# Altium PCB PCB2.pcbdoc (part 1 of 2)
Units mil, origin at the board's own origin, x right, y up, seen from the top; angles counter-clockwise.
Board outline 4625.8 x 3614.6 mil, 4 copper layers (Top Layer, Inner1, Inner2, Bottom Layer); 121 components, 127 nets, 523 pads, 246 vias.
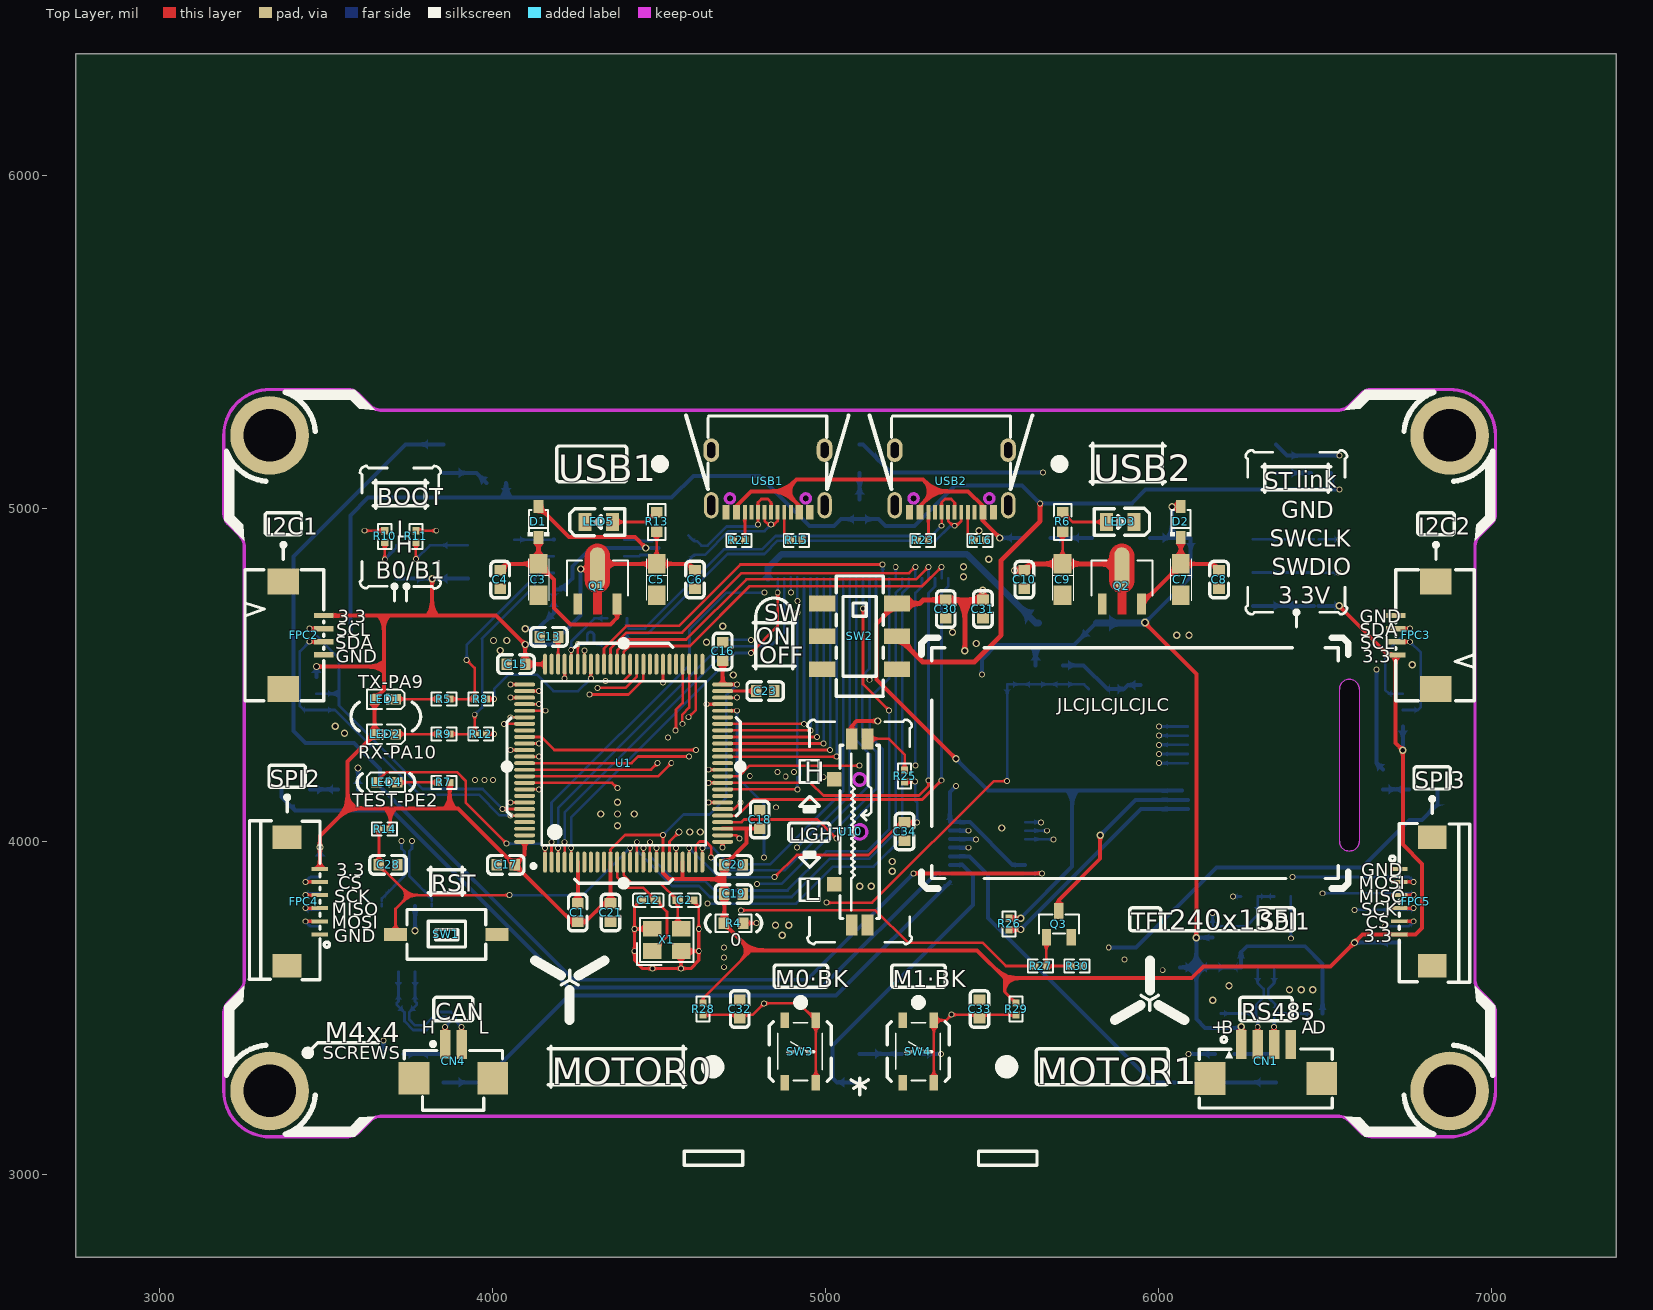
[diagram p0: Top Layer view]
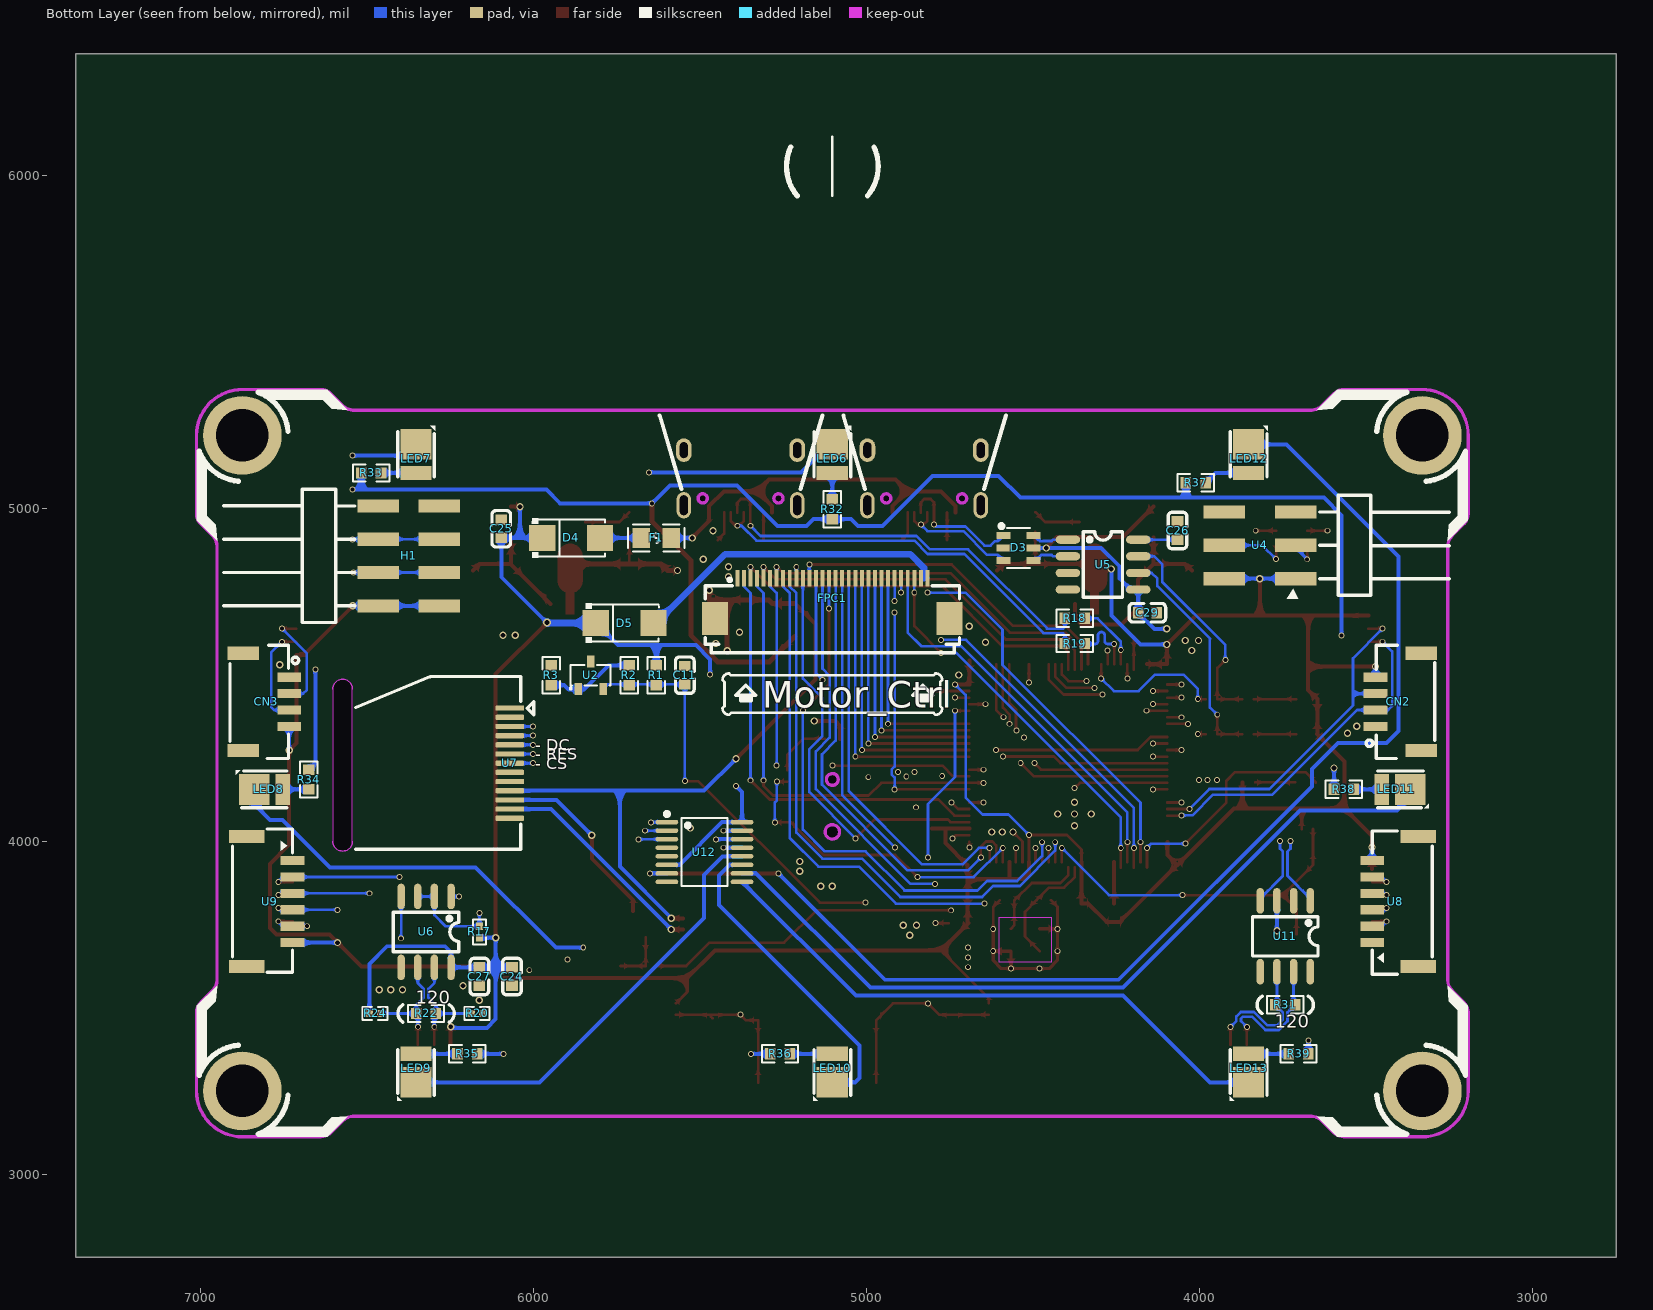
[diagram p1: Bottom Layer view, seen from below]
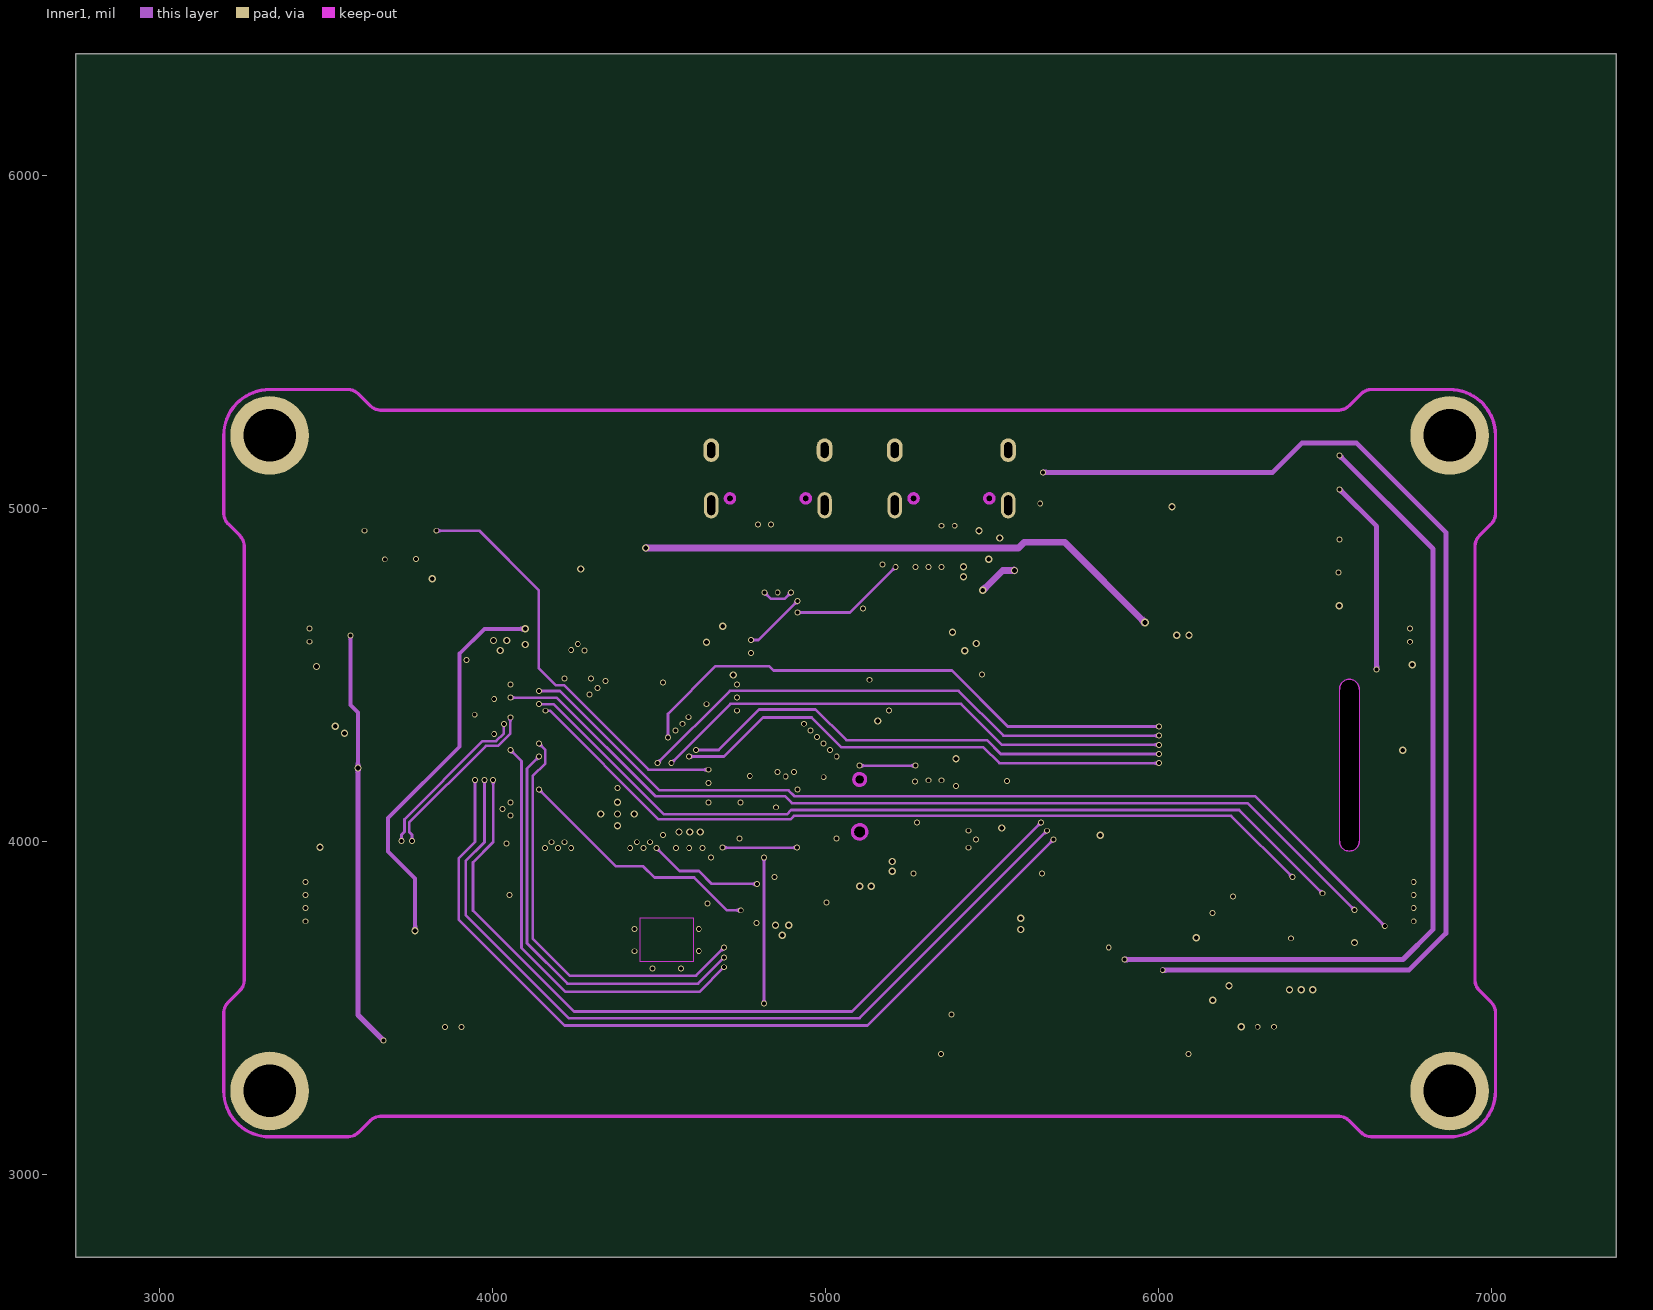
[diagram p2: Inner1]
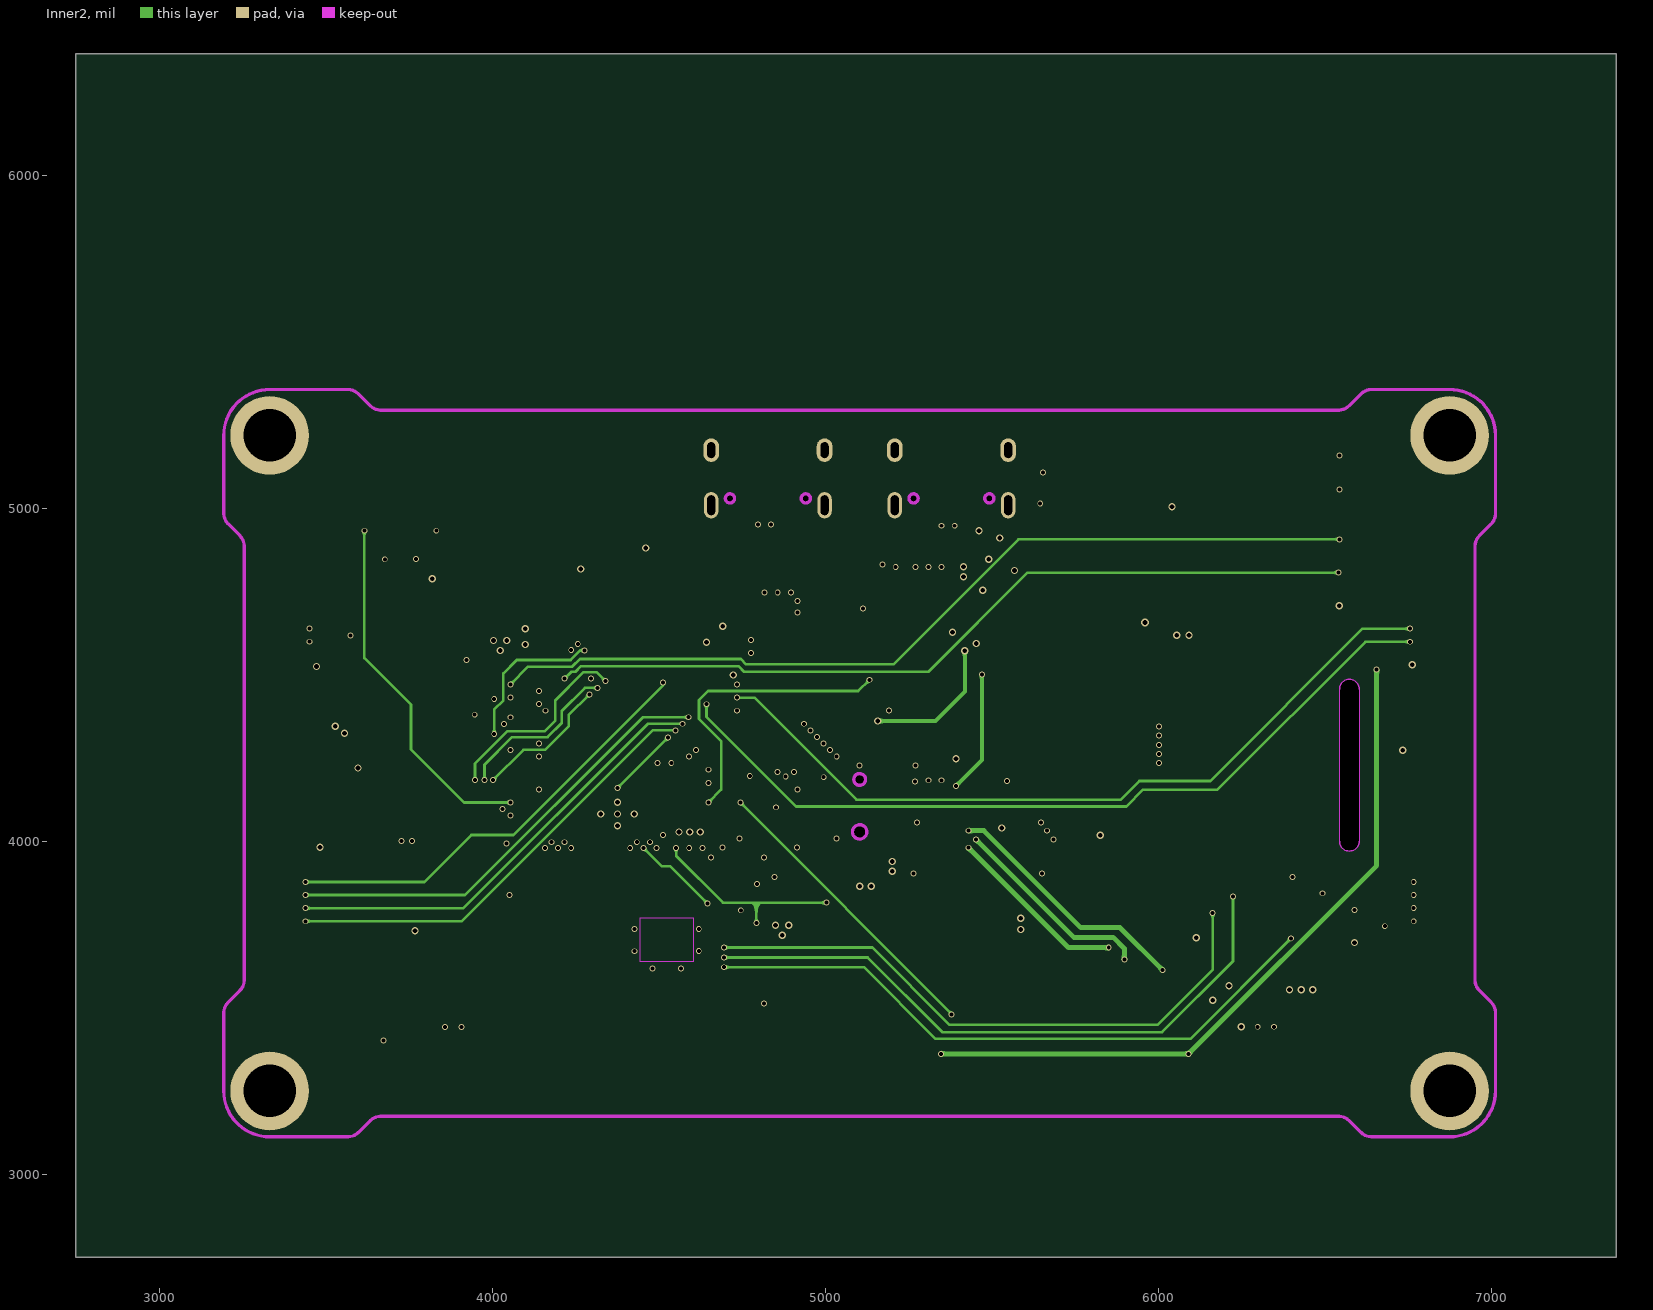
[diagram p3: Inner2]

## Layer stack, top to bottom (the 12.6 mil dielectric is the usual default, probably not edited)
Top Layer: signal copper (thickness not stored)
Dielectric: dielectric 12.6, FR-4, Dk 4.8
Inner1: signal copper (thickness not stored)
Dielectric: dielectric 12.6, FR-4, Dk 4.8
Inner2: signal copper (thickness not stored)
Dielectric: dielectric 12.6, FR-4, Dk 4.8
Bottom Layer: signal copper (thickness not stored)

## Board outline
7375.8,2750 2750,2750 2750,6364.6 7375.8,6364.6

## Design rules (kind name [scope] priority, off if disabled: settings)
BoardOutlineClearance copperThickness1oz [All] p0: genericclearance=10 ignorepadtopadclearanceinfootprint=FALSE except(0: Arc-SplitContinuation Track-SplitContinuation SMDPad-SplitContinuation THPad-SplitContinuation Via-SplitContinuation Fill-SplitContinuation Poly-SplitContinuation Region-SplitContinuation Text-SplitContinuation; 6: Track-CutoutEdge SMDPad-CutoutEdge THPad-CutoutEdge Via-CutoutEdge Region-CutoutEdge; 11.8: Track-OutlineEdge SMDPad-OutlineEdge THPad-OutlineEdge Via-OutlineEdge Fill-OutlineEdge Region-OutlineEdge Poly-OutlineEdge Text-OutlineEdge Fill-CutoutEdge)
BoardOutlineClearance copperThickness2oz [All] p0: genericclearance=10 ignorepadtopadclearanceinfootprint=FALSE except(0: Arc-SplitContinuation Track-SplitContinuation SMDPad-SplitContinuation THPad-SplitContinuation Via-SplitContinuation Fill-SplitContinuation Poly-SplitContinuation Region-SplitContinuation Text-SplitContinuation; 6: Track-CutoutEdge SMDPad-CutoutEdge THPad-CutoutEdge Via-CutoutEdge Region-CutoutEdge; 11.8: Track-OutlineEdge SMDPad-OutlineEdge THPad-OutlineEdge Via-OutlineEdge Fill-OutlineEdge Region-OutlineEdge Poly-OutlineEdge Text-OutlineEdge Fill-CutoutEdge)
Clearance copperThickness1oz [(InNet('+5V') OR InNet('DGND') OR InNet('+3.3V_1') OR InNet('+3.3V_2') OR InNet('$1N11541') OR InNet('$1N5052') OR InNet('OSC_OUT') OR InNet('OSC_IN') OR InNet('$1N13723') OR InNet('VREF') OR InNet('BACKLIGHT_ADC') OR InNet('D+') OR InNet('D-') OR InNet('USB-') OR InNet('USB+') OR InNet('$1N31567') OR InNet('USB_VCC') OR InNet('M1_ADC_C') OR InNet('M1_ADC_A') OR InNet('M1_ADC') OR InNet('M0_ADC') OR InNet('M0_ADC_C') OR InNet('M0_ADC_A') OR InNet('M0_TIM1_CH1N') OR InNet('M0_TIM1_CH1') OR InNet('M0_TIM1_CH2N') OR InNet('M0_TIM1_CH2') OR InNet('M0_TIM1_CH3N') OR InNet('M0_TIM1_CH3') OR InNet('MOTOR_EN1') OR InNet('MOTOR_EN2') OR InNet('$1N25478') OR InNet('$1N25477') OR InNet('CAN_L') OR InNet('CAN_H') OR InNet('$1N8262') OR InNet('$1N34651') OR InNet('$1N34643') OR InNet('$1N34636') OR InNet('$1N4607') OR InNet('$1N21384') OR InNet('$1N21388') OR InNet('BOOT0') OR InNet('BOOT1') OR InNet('OTG_D+') OR InNet('OTG_D-') OR InNet('$1N14257') OR InNet('$1N21387') OR InNet('BACKLIGHT') OR InNet('$1N24716') OR InNet('$1N28487') OR InNet('$1N28620') OR InNet('$1N28747') OR InNet('$1N28749') OR InNet('CH340_TX') OR InNet('CH340_RX') OR InNet('PD6') OR InNet('PD5') OR InNet('PD4') OR InNet('PA14') OR InNet('PA13') OR InNet('PA12') OR InNet('PA11') OR InNet('PC9') OR InNet('PC3') OR InNet('NRST') OR InNet('M1_TIM8_CH1N') OR InNet('M1_TIM8_CH1') OR InNet('M1_TIM8_CH2N') OR InNet('M1_TIM8_CH2') OR InNet('M1_TIM8_CH3N') OR InNet('M1_TIM8_CH3') OR InNet('M0_I2C1_SDA') OR InNet('M0_I2C1_SCL') OR InNet('M1_SPI3_MOSI') OR InNet('M1_SPI3_MISO') OR InNet('M1_SPI3_CS') OR InNet('M1_I2C2_SDA') OR InNet('M1_I2C2_SCL') OR InNet('M1_BK_BUTTON') OR InNet('M0_BK_BUTTON') OR InNet('TEST_LED') OR InNet('$1N41751') OR InNet('PA9') OR InNet('PA10') OR InNet('CAN1_TX') OR InNet('CAN1_RX') OR InNet('$1N56661') OR InNet('M1_SPI3_SCK') OR InNet('M0_BK_OUT') OR InNet('M1_BK_OUT') OR InNet('PB5') OR InNet('PB4') OR InNet('PB3') OR InNet('PD7') OR InNet('PD3') OR InNet('M0_SPI2_CS') OR InNet('M0_SPI2_SCK') OR InNet('M0_SPI2_MISO') OR InNet('M0_SPI2_MOSI') OR InNet('$1N85266') OR InNet('$1N85309') OR InNet('$1N95889') OR InNet('LEDC') OR InNet('LEDB') OR InNet('LEDA') OR InNet('$1N102783') OR InNet('$1N102744') OR InNet('$1N102997') OR InNet('$1N103001') OR InNet('$1N103337') OR InNet('$1N103341') OR InNet('$1N103422') OR InNet('$1N103426') OR InNet('$1N103507') OR InNet('$1N103511') OR InNet('$1N103592') OR InNet('$1N103596') OR InNet('$1N103677') OR InNet('$1N103681') OR InNet('$1N103762') OR InNet('$1N103766') OR InNet('VCC_+3.3V_2') OR InNet('$1N129348') OR InNet('PA7') OR InNet('PA1') OR InNet('PC2'))] p1: gap=7 ignorepadtopadclearanceinfootprint=FALSE except(4: Track-Track; 6: Track-SMDPad SMDPad-SMDPad Track-THPad SMDPad-THPad THPad-THPad Track-Via SMDPad-Via THPad-Via Via-Via SMDPad-Fill THPad-Fill Via-Fill Fill-Fill Track-Region SMDPad-Region THPad-Region Via-Region Region-Region Track-Poly SMDPad-Poly THPad-Poly Via-Poly Fill-Poly Region-Poly Poly-Poly Track-Text SMDPad-Text THPad-Text Via-Text Fill-Text Region-Text Poly-Text Text-Text; 6.9: Track-Hole SMDPad-Hole THPad-Hole Via-Hole Fill-Hole Region-Hole Poly-Hole Text-Hole Sheet-Hole; 11.8: Track-Fill Fill-Region Track-Sheet SMDPad-Sheet THPad-Sheet Via-Sheet Fill-Sheet Region-Sheet Poly-Sheet Text-Sheet)
Clearance copperThickness2oz [All] p1: gap=7 ignorepadtopadclearanceinfootprint=FALSE except(6: Track-SMDPad SMDPad-SMDPad Track-THPad SMDPad-THPad THPad-THPad Track-Via SMDPad-Via THPad-Via Via-Via SMDPad-Fill THPad-Fill Via-Fill Fill-Fill Track-Region SMDPad-Region THPad-Region Via-Region Region-Region Track-Poly SMDPad-Poly THPad-Poly Via-Poly Fill-Poly Region-Poly Poly-Poly Track-Text SMDPad-Text THPad-Text Via-Text Fill-Text Region-Text Poly-Text Text-Text; 6.9: Track-Hole SMDPad-Hole THPad-Hole Via-Hole Fill-Hole Region-Hole Poly-Hole Text-Hole Sheet-Hole; 8: Track-Track; 11.8: Track-Fill Fill-Region Track-Sheet SMDPad-Sheet THPad-Sheet Via-Sheet Fill-Sheet Region-Sheet Poly-Sheet Text-Sheet)
DiffPairsRouting differentialPair [All] p1: maxuncoupledlength=10 minlimit=6 maxlimit=6 mostfreqgap=6 toplayer_minwidth=5 toplayer_prefwidth=10 toplayer_maxwidth=100 bottomlayer_minwidth=5 bottomlayer_prefwidth=10 bottomlayer_maxwidth=100 midlayer1_minwidth=5 midlayer1_prefwidth=10 midlayer1_maxwidth=100 midlayer2_minwidth=5 midlayer2_prefwidth=10 midlayer2_maxwidth=100
PasteMaskExpansion pasteMaskExpansion [All] p1: expansion=0
PlaneConnect innerPlane [All] p1: planeconnectstyle=Relief reliefexpansion=20 reliefentries=4 reliefconductorwidth=10 reliefairgap=10
PolygonConnect copperRegion [All] p1: connectstyle=Direct reliefentries=4 reliefconductorwidth=10 polygonreliefangle="90 Angle" airgapwidth=10
RoutingVias viaSize [All] p1: viastyle="Through Hole" holewidth=12 minholewidth=11.8 maxholewidth=248 width=24 minwidth=17.7 maxwidth=393.7
SolderMaskExpansion solderMaskExpansion [All] p1: useseparateexpansions=TRUE expansion=2 expansionbottom=2
Width copperThickness1oz [All] p1: maxlimit=100 minlimit=5 preferedwidth=10
Width copperThickness2oz [All] p1: maxlimit=100 minlimit=8 preferedwidth=10

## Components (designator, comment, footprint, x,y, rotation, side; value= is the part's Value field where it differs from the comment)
C1 "CL10A105KB8NNNC" C0603 4257.4,3785.7 r90 top
C2 "0402CG140J500NT" C0402 4579.3,3822.79 r0 top
C3 "TAJA226K010RNJ" CASE-A_3216 4139.5,4785.5 r270 top
C4 "CC0603KRX7R9BB104" C0603 4024.5,4785.5 r90 top
C5 "TAJA226K010RNJ" CASE-A_3216 4494.5,4785.5 r270 top
C6 "CC0603KRX7R9BB104" C0603 4609.5,4785.5 r90 top
C7 "TAJA226K010RNJ" CASE-A_3216 6068.31,4785.53 r270 top
C8 "CC0603KRX7R9BB104" C0603 6183.31,4785.53 r90 top
C9 "TAJA226K010RNJ" CASE-A_3216 5713.31,4785.53 r270 top
C10 "CC0603KRX7R9BB104" C0603 5598.31,4785.53 r90 top
C11 "CGA0603X7R104K500JT" C0603 5546.9,4498.6 r270 bottom
C12 "0402CG140J500NT" C0402 4469.3,3822.79 r180 top
C13 "CL10A225KO8NNNC" C0603 4170.74,4613.6 r0 top
C15 "CGA0603X7R104K500JT" C0603 4071.74,4531.54 r0 top
C16 "CGA0603X7R104K500JT" C0603 4692.68,4570.1 r270 top
C17 "CGA0603X7R104K500JT" C0603 4041.24,3929.04 r0 top
C18 "CGA0603X7R104K500JT" C0603 4803.9,4065.04 r270 top
C19 "CGA0603X7R104K500JT" C0603 4725.15,3841.55 r180 top
C20 "CGA0603X7R104K500JT" C0603 4725.15,3929.05 r180 top
C21 "CGA0603X7R104K500JT" C0603 4355.9,3785.7 r90 top
C23 "CL10A225KO8NNNC" C0603 4820.24,4451.05 r180 top
C24 "CL10A475KO8NNNC" C0603 6065.9,3593.54 r90 bottom
C25 "CL10A225KO8NNNC" C0603 6098.1,4938.16 r270 bottom
C26 "CGA0603X7R104K500JT" C0603 4067.43,4932.9 r90 bottom
C27 "CGA0603X7R104K500JT" C0603 6163.9,3593.54 r90 bottom
C28 "CGA0603X7R104K500JT" C0603 3687.9,3929.05 r180 top
C29 "CGA0603X7R104K500JT" C0603 4157.84,4686 r0 bottom
C30 "CC0603KRX7R9BB104" C0603 5362.4,4697 r90 top
C31 "CL10A475KO8NNNC" C0603 5473.9,4697 r90 top
C32 "CGA0603X7R104K500JT" C0603 4743.9,3496.1 r270 top
C33 "CGA0603X7R104K500JT" C0603 5463.9,3496.1 r270 top
C34 "CL10A475KO8NNNC" C0603 5238.87,4029 r270 top
CN1 "HC-1.25-4PWT" CONN-SMD_4P-P1.25-HC-1.25-4PWT 6323.9,3338.6 r0 top
CN2 "HC-GH-4PWT_C2845399" CONN-SMD_HC-GH-4PWT 3403.9,4418.6 r90 bottom
CN3 "HC-GH-4PWT_C2845399" CONN-SMD_HC-GH-4PWT 6803.9,4418.6 r270 bottom
CN4 "HC-1.25-2PWT" CONN-SMD_2P-P1.25-HC-1.25-2PWT 3883.9,3338.6 r0 top
D1 "1N5819WS_C191023" SOD-323_L1.8-W1.3-LS2.5-RD 4139.5,4958.6 r90 top
D2 "1N5819WS_C191023" SOD-323_L1.8-W1.3-LS2.5-RD 6068.3,4958.6 r90 top
D3 "USBLC6-2SC6" SOT-23-6_L2.9-W1.6-P0.95-LS2.8-BL 4544.9,4880.6 r270 bottom
D4 "SS34_C8678" SMA_L4.3-W2.6-LS5.2-RD 5888.5,4910.6 r180 bottom
D5 "SS34_C8678" SMA_L4.3-W2.6-LS5.2-RD 5727.6,4655.2 r180 bottom
F1 "SMD0805-100" F0805 5632.4,4910.6 r0 bottom
FPC1 "FPC-05F-30PH20" FPC-SMD_30P-P0.50_XUNPU_FPC-05F-30PH20 5103.9,4729.6 r180 bottom
FPC2 "AFA01-S04FCC-00" FPC-SMD_AFA01-S04FCC-00 3433.9,4618.6 r270 top
FPC3 "AFA01-S04FCC-00" FPC-SMD_AFA01-S04FCC-00 6773.9,4618.6 r90 top
FPC4 "AFA01-S06FCC-00" FPC-SMD_6P-P1.00_AFA01-S06 3433.9,3818.6 r270 top
FPC5 "AFA01-S06FCC-00" FPC-SMD_6P-P1.00_AFA01-S06 6773.9,3818.6 r90 top locked
H1 "PZ254-2-04-WS" HDR-SMD_8P-P2.54-H-M-R2-C4_2 6376.1,4856.8 r270 bottom
LED1 "XL-1608UGC-04" LED0603-RD_GREEN 3678.9,4426.6 r180 top
LED2 "XL-1608UBC-04" LED0603-RD_BLUE 3679.41,4321.52 r180 top
LED3 "KT-0805Y" LED0805-R-RD 5886.8,4958.6 r180 top
LED4 "NCD0603R1_C84263" LED0603-RD_RED 3683.32,4176.6 r0 top
LED5 "KT-0805Y" LED0805-R-RD 4320.5,4958.6 r0 top
LED6 "HL-AM-2835H489W-S1-08HL-HR3" LED-SMD_L3.3-W2.8-RD 5103.9,5148.6 r270 bottom
LED7 "HL-AM-2835H489W-S1-08HL-HR3" LED-SMD_L3.3-W2.8-RD 6353.9,5148.6 r270 bottom
LED8 "HL-AM-2835H489W-S1-08HL-HR3" LED-SMD_L3.3-W2.8-RD 6796.81,4155.61 r180 bottom
LED9 "HL-AM-2835H489W-S1-08HL-HR3" LED-SMD_L3.3-W2.8-RD 6353.9,3318.6 r90 bottom
LED10 "HL-AM-2835H489W-S1-08HL-HR3" LED-SMD_L3.3-W2.8-RD 5103.9,3318.6 r90 bottom
LED11 "HL-AM-2835H489W-S1-08HL-HR3" LED-SMD_L3.3-W2.8-RD 3410.99,4155.61 r0 bottom
LED12 "HL-AM-2835H489W-S1-08HL-HR3" LED-SMD_L3.3-W2.8-RD 3853.9,5148.6 r270 bottom
LED13 "HL-AM-2835H489W-S1-08HL-HR3" LED-SMD_L3.3-W2.8-RD 3853.9,3318.6 r90 bottom
Q1 "AMS1117-3.3V_C5120796" SOT-89-3_L4.5-W2.5-P1.50-LS4.2-BR 4316.5,4765.84 r270 top locked
Q2 "AMS1117-3.3V_C5120796" SOT-89-3_L4.5-W2.5-P1.50-LS4.2-BR 5891.3,4765.84 r270 top locked
Q3 "S8050" SOT-23-3_L2.9-W1.3-P1.90-LS2.4-BR 5701.9,3751.1 r270 top
R1 "0603WAF1001T5E" R0603 5632.4,4498.6 r270 bottom
R2 "0603WAF1501T5E" R0603 5713.88,4498.6 r270 bottom
R3 "RC0603FR-074K7L" R0603 5947.9,4498.6 r270 bottom
R4 "0603WAF0000T5E" R0603 4725.15,3754.04 r0 top
R5 "FRC0402F3001TS" R0402 3855.71,4426.6 r0 top
R6 "0603WAF3001T5E" R0603 5713.3,4958.6 r270 top
R7 "FRC0402F3001TS" R0402 3855.71,4176.81 r0 top
R8 "0402WGF1000TCE" R0402 3966.24,4426.6 r0 top
R9 "FRC0402J102 TS" R0402 3855.71,4321.71 r0 top
R10 "0402WGF1002TCE" R0402 3677.88,4915.39 r270 top
R11 "0402WGF1002TCE" R0402 3771.4,4915.39 r270 top
R12 "0402WGF1000TCE" R0402 3966.24,4321.71 r0 top
R13 "0603WAF3001T5E" R0603 4494.5,4958.6 r270 top
R14 "0402WGF1002TCE" R0402 3677.34,4036.44 r0 top
R15 "0402WGF5101TCE" R0402 4914.24,4903.64 r180 top
R16 "0402WGF5101TCE" R0402 5465.44,4903.64 r180 top
R17 "0402WGF1002TCE" R0402 6163.9,3727.6 r90 bottom
R18 "0603WAF0000T5E" R0603 4375.74,4669.1 r180 bottom
R19 "0603WAF0000T5E" R0603 4375.74,4593.6 r180 bottom
R20 "FRC0402J102 TS" R0402 6170.9,3482.79 r180 bottom
R21 "0402WGF5101TCE" R0402 4741.68,4903.64 r0 top
R22 "0603WAF1200T5E" R0603 6323.9,3482.79 r180 bottom
R23 "0402WGF5101TCE" R0402 5293.52,4903.64 r0 top
R24 "FRC0402J102 TS" R0402 6476.9,3482.79 r0 bottom
R25 "FRC0402J102 TS" R0402 5238.87,4195.8 r90 top
R26 "0402WGF200JTCE" R0402 5552.4,3751.6 r90 top
R27 "0402WGF1002TCE" R0402 5647.18,3625.27 r0 top
R28 "0402WGF1002TCE" R0402 4633.9,3496.1 r270 top
R29 "0402WGF1002TCE" R0402 5573.9,3496.1 r270 top
R30 "0402WGF1002TCE" R0402 5756.9,3625.27 r0 top
R31 "0603WAF1200T5E" R0603 3743.9,3508.6 r180 bottom
R32 "0603WAF1000T5E" R0603 5103.9,4996.6 r270 bottom
R33 "0603WAF1000T5E" R0603 6488.9,5105.8 r0 bottom
R34 "0603WAF1000T5E" R0603 6675.83,4185.27 r90 bottom
R35 "0603WAF1000T5E" R0603 6199.9,3361.4 r180 bottom
R36 "0603WAF1000T5E" R0603 5260.9,3361.4 r0 bottom
R37 "0603WAF1000T5E" R0603 4012.49,5076.28 r0 bottom
R38 "0603WAF1000T5E" R0603 3567.84,4155.61 r0 bottom
R39 "0603WAF1000T5E" R0603 3703.9,3361.4 r180 bottom
SW1 "TS-1107S-16" SW-SMD_L6.0-W3.7-LS8.0 3862.9,3720.2 r180 top
SW2 "MST22D18G2" SW-SMD_MST22D18G2 5103.9,4615.1 r270 top locked
SW3 "K2-1808SN-A3SW-01" 椭圆白头按钮开关 4926.73,3368.21 r90 top
SW4 "K2-1808SN-A3SW-01" 椭圆白头按钮开关 5281.07,3368.21 r90 top
U1 "STM32F407VGT6" LQFP-100_L14.0-W14.0-P0.50-LS16.0-BL 4395.24,4234.35 r0 top locked
U2 "TL431_C963380" SOT-23-3_L2.9-W1.4-P1.90-LS2.6-BR 5829.49,4498.6 r270 bottom
U4 "PZ254-2-03-WS" HDR-SMD_6P-P2.54-H-M-R2-C3-LS17.0 3819.9,4888.6 r90 bottom locked
U5 "CH340N" SOP-8_L4.9-W3.9-P1.27-LS6.0-BL 4291.02,4830.62 r270 bottom
U6 "MAX13488EESA+T" SOIC-8_L5.0-W4.0-P1.27-LS6.0-BL 6323.9,3727.6 r0 bottom
U7 "1.14 TFT_13P" "1.14 TFT_13P" 5930.67,4234.35 r0 top locked
U8 "HC-GH-6PWT" CONN-SMD_6P-P1.25_HCTL_HC-GH-6PWT 3413.9,3818.6 r90 bottom
U9 "HC-GH-6PWT" CONN-SMD_6P-P1.25_HCTL_HC-GH-6PWT 6793.9,3818.6 r270 bottom
U10 "RS08U111Z001" RS08U111Z001 5103.9,4028 r0 top
U11 "TJA1050T/CM,118" SOIC-8_L5.0-W4.0-P1.27-LS6.0-BL 3743.9,3714.6 r0 bottom
U12 "SN74HC138PWR" TSSOP-16_L5.0-W4.4-P0.65-LS6.4-BL 5487.9,3967.6 r270 bottom
USB1 "TYPE-C 16PIN 2MD(073)" USB-C-SMD_TYPE-C-6PIN-2MD-073 4828.31,5080.8 r180 top locked
USB2 "TYPE-C 16PIN 2MD(073)" USB-C-SMD_TYPE-C-6PIN-2MD-073 5379.49,5080.8 r180 top locked
X1 "X322525MOB4SI" CRYSTAL-SMD_4P-L3.2-W2.5-BL 4524.8,3703.54 r0 top

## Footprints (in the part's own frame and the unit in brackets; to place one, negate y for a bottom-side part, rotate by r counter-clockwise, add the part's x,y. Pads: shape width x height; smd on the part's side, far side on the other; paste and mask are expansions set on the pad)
"1.14 TFT_13P" [mm]
  rrect50% 2.2x0.4 smd far side: 1(3.6,4.2) 2(3.6,3.5) 3(3.6,2.8) 4(3.6,2.1) 5(3.6,1.4) 6(3.6,0.7) 7(3.6,0) 8(3.6,-0.7) 9(3.6,-1.4) 10(3.6,-2.1) 11(3.6,-2.8) 12(3.6,-3.5) 13(3.6,-4.2)
  Board Outline Layer lines w0.025: 16.35,-6.705 ccw(c16.35,-5.955) 17.1,-5.955 17.1,5.65 ccw(c16.35,5.65) 16.35,6.4 ; 16.35,-6.705 16.35,-6.705 ; 16.35,-6.705 cw(c16.35,-5.955) 15.6,-5.955 15.6,5.65 cw(c16.35,5.65) 16.35,6.4 ; 16.35,6.4 16.35,6.4
  Board Outline Layer region: 16.35,6.4 16.35,6.4 16.637,6.343 16.88,6.18 17.043,5.937 17.1,5.65 17.1,5.65 17.1,-5.955 17.043,-6.242 16.88,-6.485 16.637,-6.648 16.35,-6.705 16.35,-6.705 16.35,-6.705 16.063,-6.648 15.82,-6.485 15.657,-6.242 15.6,-5.955 15.6,-5.955 15.6,5.65 15.657,5.937 15.82,6.18 16.063,6.343 16.35,6.4
  Multi-Layer board cut-out: 16.35,6.4 16.35,6.4 16.637,6.343 16.88,6.18 17.043,5.937 17.1,5.65 17.1,5.65 17.1,-5.955 17.043,-6.242 16.88,-6.485 16.637,-6.648 16.35,-6.705 16.35,-6.705 16.35,-6.705 16.063,-6.648 15.82,-6.485 15.657,-6.242 15.6,-5.955 15.6,-5.955 15.6,5.65 15.657,5.937 15.82,6.18 16.063,6.343 16.35,6.4
  silkscreen extent -16.28,-9.56 16.28,9.56
C0402 [mm]
  rect 0.79x0.54 smd: 1(-0.545,0) 2(0.545,0)
  silkscreen extent -1.17,-0.5 1.17,0.5
C0603 [mm]
  rect 0.8x0.9 smd: 1(-0.7,0) 2(0.7,0)
  silkscreen extent -1.39,-0.71 1.39,0.71
CASE-A_3216 [mil]
  rect 59.05x53.5 smd: 1(-47.24,0) 2(47.24,0)
  silkscreen extent -63,-32 63,32
CONN-SMD_2P-P1.25-HC-1.25-2PWT [mm]
  rect 0.8x2.2 smd: 1(-0.625,1.285) 2(0.625,1.285)
  rect 2.35x2.5 smd: 3(-3.005,-1.285) 4(3.005,-1.285)
  silkscreen extent -3.75,-3.73 3.75,1.48
CONN-SMD_4P-P1.25-HC-1.25-4PWT [mm]
  rect 0.8x2.2 smd: 1(-1.875,1.3) 2(-0.625,1.3) 3(0.625,1.3) 4(1.875,1.3)
  rect 2.35x2.5 smd: 5(4.255,-1.3) 6(-4.255,-1.3)
  silkscreen extent -5.08,-3.55 5.06,1.88
CONN-SMD_6P-P1.25_HCTL_HC-GH-6PWT [mm]
  rect 0.7x1.8 smd: 1(-3.125,1.75) 2(-1.875,1.75) 3(-0.625,1.75) 4(0.625,1.75) 5(1.875,1.75) 6(3.125,1.75)
  rect 1x2.7 smd: 7(4.955,-1.75) 8(-4.955,-1.75)
  silkscreen extent -5.54,-2.82 5.38,1.75
CONN-SMD_HC-GH-4PWT [mm]
  rect 0.7x1.8 smd: 1(-1.875,1.75) 2(-0.625,1.75) 3(0.625,1.75) 4(1.875,1.75)
  rect 1x2.4 smd: 5(3.705,-1.75) 6(-3.705,-1.75)
  silkscreen extent -4.32,-2.76 4.32,2.47
CRYSTAL-SMD_4P-L3.2-W2.5-BL [mm]
  rect 1.4x1.2 smd: 1(-1.1,-0.85) 2(1.1,-0.85) 3(1.1,0.85) 4(-1.1,0.85)
  silkscreen extent -2.26,-1.91 2.03,1.68
F0805 [mm]
  rect 1.335x1.5 smd: 1(-1.142,0) 2(1.142,0)
  silkscreen extent -2.16,-1.02 2.16,1.02
FPC-SMD_6P-P1.00_AFA01-S06 [mil]
  rect 11.8x49.2 smd: 1(98.4,49.2) 2(59.1,49.2) 3(19.7,49.2) 4(-19.7,49.2) 5(-59,49.2) 6(-98.4,49.2)
  rect 70.9x86.6 smd: 7(192.9,-49.2) 8(-192.9,-49.2)
  silkscreen extent -242,-163 235,78
FPC-SMD_30P-P0.50_XUNPU_FPC-05F-30PH20 [mm]
  rect 0.3x1.25 smd: 1(-7.25,1.538) 2(-6.75,1.538) 3(-6.25,1.538) 4(-5.75,1.538) 5(-5.25,1.538) 6(-4.75,1.538) 7(-4.25,1.538) 8(-3.75,1.538) 9(-3.25,1.538) 10(-2.75,1.538) 11(-2.25,1.538) 12(-1.75,1.538) 13(-1.25,1.538) 14(-0.75,1.538) 15(-0.25,1.538) 16(0.25,1.538) 17(0.75,1.538) 18(1.25,1.538) 19(1.75,1.538) 20(2.25,1.538) 21(2.75,1.538) 22(3.25,1.538) 23(3.75,1.538) 24(4.25,1.538) 25(4.75,1.538) 26(5.25,1.538) 27(5.75,1.538) 28(6.25,1.538) 29(6.75,1.538) 30(7.25,1.538)
  rect 2x2.5 smd: 31(8.94,-1.538) 32(-8.94,-1.538)
  silkscreen extent -9.7,-4.15 9.7,1.53
FPC-SMD_AFA01-S04FCC-00 [mil]
  rect 15.7x59.1 smd: 1(-59.1,60.5) 2(-19.7,60.5) 3(19.6,60.5) 4(59,60.5)
  rect 78.7x94.5 smd: 5(-161.4,-60.5) 6(161.4,-60.5)
  silkscreen extent -197,-176 197,60
HDR-SMD_6P-P2.54-H-M-R2-C3-LS17.0 [mm]
  rect 1.02x3.17 smd: 1(-2.54,-2.725) 2(-2.54,2.725) 3(0,-2.725) 4(0,2.725) 5(2.54,-2.725) 6(2.54,2.725)
  silkscreen extent -4.06,-14.46 3.81,-2.03
HDR-SMD_8P-P2.54-H-M-R2-C4_2 [mm]
  rect 1x3.17 smd: 1(-3.81,2.33) 2(-3.81,-2.33) 3(-1.27,2.33) 4(-1.27,-2.33) 5(1.27,2.33) 6(1.27,-2.33) 7(3.81,2.33) 8(3.81,-2.33)
  silkscreen extent -5.08,-14.11 5.08,-4.1
LED0603-RD_BLUE [mil]
  rect 31.5x31.5 smd: 1(-31.5,-0.1) 2(31.5,0.1)
  silkscreen extent -59,-29 55,30
LED0603-RD_GREEN [mm]
  rect 0.8x0.8 smd: 1(-0.799,-0.003) 2(0.799,0.003)
  silkscreen extent -1.49,-0.75 1.39,0.76
LED0603-RD_RED [mm]
  rect 0.8x0.8 smd: 1(-0.8,-0.003) 2(0.8,0.003)
  silkscreen extent -1.49,-0.75 1.39,0.76
LED0805-R-RD [mm]
  rect 1x1.4 smd: 1(1.05,0) 2(-1.05,0)
  silkscreen extent -2.22,-1.04 1.99,1.01
LED-SMD_L3.3-W2.8-RD [mm]
  rect 2.33x2.38 smd: 1(-1.088,0)
  rect 1.1x2.38 smd: 2(1.088,0)
  silkscreen extent -2.5,-1.4 1.4,1.45
LQFP-100_L14.0-W14.0-P0.50-LS16.0-BL [mm]
  oval 0.3x1.6 smd: 1(-6,-7.55) 2(-5.5,-7.55) 3(-5,-7.55) 4(-4.5,-7.55) 5(-4,-7.55) 6(-3.5,-7.55) 7(-3,-7.55) 8(-2.5,-7.55) 9(-2,-7.55) 10(-1.5,-7.55) 11(-1,-7.55) 12(-0.5,-7.55) 13(0,-7.55) 14(0.5,-7.55) 15(1,-7.55) 16(1.5,-7.55) 17(2,-7.55) 18(2.5,-7.55) 19(3,-7.55) 20(3.5,-7.55) 21(4,-7.55) 22(4.5,-7.55) 23(5,-7.55) 24(5.5,-7.55) 25(6,-7.55) 51(6,7.55) 52(5.5,7.55) 53(5,7.55) 54(4.5,7.55) 55(4,7.55) 56(3.5,7.55) 57(3,7.55) 58(2.5,7.55) 59(2,7.55) 60(1.5,7.55) 61(1,7.55) 62(0.5,7.55) 63(0,7.55) 64(-0.5,7.55) 65(-1,7.55) 66(-1.5,7.55) 67(-2,7.55) 68(-2.5,7.55) 69(-3,7.55) 70(-3.5,7.55) 71(-4,7.55) 72(-4.5,7.55) 73(-5,7.55) 74(-5.5,7.55) 75(-6,7.55)
  oval 1.6x0.3 smd: 26(7.55,-6) 27(7.55,-5.5) 28(7.55,-5) 29(7.55,-4.5) 30(7.55,-4) 31(7.55,-3.5) 32(7.55,-3) 33(7.55,-2.5) 34(7.55,-2) 35(7.55,-1.5) 36(7.55,-1) 37(7.55,-0.5) 38(7.55,0) 39(7.55,0.5) 40(7.55,1) 41(7.55,1.5) 42(7.55,2) 43(7.55,2.5) 44(7.55,3) 45(7.55,3.5) 46(7.55,4) 47(7.55,4.5) 48(7.55,5) 49(7.55,5.5) 50(7.55,6) 76(-7.55,6) 77(-7.55,5.5) 78(-7.55,5) 79(-7.55,4.5) 80(-7.55,4) 81(-7.55,3.5) 82(-7.55,3) 83(-7.55,2.5) 84(-7.55,2) 85(-7.55,1.5) 86(-7.55,1) 87(-7.55,0.5) 88(-7.55,0) 89(-7.55,-0.5) 90(-7.55,-1) 91(-7.55,-1.5) 92(-7.55,-2) 93(-7.55,-2.5) 94(-7.55,-3) 95(-7.55,-3.5) 96(-7.55,-4) 97(-7.55,-4.5) 98(-7.55,-5) 99(-7.55,-5.5) 100(-7.55,-6)
  silkscreen extent -7.03,-8 6.25,6.25
R0402 [mm]
  rect 0.566x0.54 smd: 1(-0.433,0) 2(0.433,0)
  silkscreen extent -0.94,-0.5 0.94,0.5
R0603 [mil]
  rect 31.75x34.02 smd: 1(-29.66,0) 2(29.66,0)
  silkscreen extent -55,-26 55,26
RS08U111Z001 [mm]
  rrect5% 0.9x1.6 smd: 1(-0.6,7.1) 2(0.6,7.1) 3(0.6,-7.1) 4(-0.6,-7.1)
  rrect5% 1.1x1.1 smd: 5(-1.95,-4) 6(-1.95,4)
  Board Outline Layer circle w0.025: c0,0 r0.55
  Board Outline Layer circle w0.025: c0,4 r0.45
  Board Outline Layer circle w0.254: c0,0 r0.55
  Board Outline Layer circle w0.254: c0,4 r0.45
  Multi-Layer board cut-out: 0.55,0 0.474,0.272 0.273,0.47 0,0.543 -0.273,0.47 -0.474,0.272 -0.55,0 -0.55,0 -0.474,-0.272 -0.273,-0.47 0,-0.543 0.273,-0.47 0.474,-0.272 0.55,0
  Multi-Layer board cut-out: 0.45,4 0.405,4.195 0.281,4.352 0.1,4.439 -0.1,4.439 -0.281,4.352 -0.406,4.195 -0.45,4 -0.45,4 -0.406,3.805 -0.281,3.648 -0.1,3.561 0.1,3.561 0.281,3.648 0.405,3.805 0.45,4
  silkscreen extent -1.5,-6.6 1.5,6.6
SMA_L4.3-W2.6-LS5.2-RD [mm]
  rect 2x2 smd: 1(-2.2,0) 2(2.2,0)
  silkscreen extent -2.98,-1.5 2.6,1.5
SOD-323_L1.8-W1.3-LS2.5-RD [mm]
  rect 1x0.75 smd: 1(-1.173,0) 2(1.173,0)
  silkscreen extent -1.08,-0.8 0.9,0.8
SOIC-8_L5.0-W4.0-P1.27-LS6.0-BL [mil]
  oval 22.38x76.78 smd: 1(-75,-106.5) 2(-25,-106.5) 3(25,-106.5) 4(75,-106.5) 5(75,106.5) 6(25,106.5) 7(-25,106.5) 8(-75,106.5)
  silkscreen extent -98,-59 98,59
SOP-8_L4.9-W3.9-P1.27-LS6.0-BL [mm]
  oval 0.63x1.865 smd: 1(-1.905,-2.682) 2(-0.635,-2.682) 3(0.635,-2.682) 4(1.905,-2.682) 5(1.905,2.682) 6(0.635,2.682) 7(-0.635,2.682) 8(-1.905,2.682)
  silkscreen extent -2.5,-1.5 2.5,1.48
SOT-23-3_L2.9-W1.3-P1.90-LS2.4-BR [mm]
  rect 1.25x0.7 smd: 1(1,-0.95) 2(1,0.95) 3(-1,0)
  silkscreen extent -0.73,-1.53 0.73,1.53
SOT-23-3_L2.9-W1.4-P1.90-LS2.6-BR [mm]
  rect 0.91x0.6 smd: 1(1.055,-0.955) 2(1.055,0.955) 3(-1.055,0)
  silkscreen extent -0.78,-1.6 1.09,1.53
SOT-23-6_L2.9-W1.6-P0.95-LS2.8-BL [mil]
  rect 20.95x42.2 smd: 1(-37.4,-45.24) 2(0,-45.24) 3(37.4,-45.24) 4(37.4,45.24) 5(0,45.24) 6(-37.4,45.24)
  silkscreen extent -72,-57 61,35
SOT-89-3_L4.5-W2.5-P1.50-LS4.2-BR [mm]
  rect 1.575x0.672 smd: 1(1.356,-1.5) 3(1.356,1.5)
  oval 3.226x1.14 smd: 2(-1.356,0)
  Top Layer region: -2.283,0.95 -0.429,0.95 -0.384,0.949 -0.34,0.946 -0.296,0.94 -0.252,0.933 -0.208,0.924 -0.165,0.912 -0.123,0.899 -0.081,0.884 -0.04,0.866 0,0.847 0.04,0.826 0.078,0.803 0.115,0.779 0.151,0.752 0.185,0.724 0.219,0.695 0.251,0.664 0.281,0.631 0.31,0.597 0.337,0.562 0.362,0.525 0.386,0.488 0.408,0.449 0.428,0.409 0.447,0.33 2.144,0.33 2.144,-0.33 0.447,-0.33 0.428,-0.409 0.408,-0.449 0.386,-0.488 0.362,-0.526 0.337,-0.562 0.31,-0.597 0.281,-0.631 0.251,-0.664 0.219,-0.695 0.185,-0.725 0.151,-0.753 0.115,-0.779 0.078,-0.804 0.04,-0.827 0,-0.848 -0.04,-0.867 -0.081,-0.884 -0.123,-0.899 -0.165,-0.913 -0.208,-0.924 -0.252,-0.934 -0.296,-0.941 -0.34,-0.946 -0.384,-0.949 -0.429,-0.95 -2.283,-0.95 -2.328,-0.949 -2.372,-0.946 -2.416,-0.941 -2.46,-0.934 -2.504,-0.924 -2.547,-0.913 -2.589,-0.899 -2.631,-0.884 -2.672,-0.867 -2.713,-0.848 -2.752,-0.827 -2.79,-0.804 -2.827,-0.779 -2.863,-0.753 -2.898,-0.725 -2.931,-0.695 -2.963,-0.664 -2.993,-0.631 -3.022,-0.597 -3.049,-0.562 -3.075,-0.526 -3.098,-0.488 -3.12,-0.449 -3.141,-0.409 -3.159,-0.369 -3.175,-0.327 -3.189,-0.285 -3.202,-0.242 -3.212,-0.199 -3.22,-0.155 -3.227,-0.111 -3.231,-0.067 -3.233,-0.022 -3.233,0.022 -3.231,0.067 -3.227,0.111 -3.22,0.155 -3.212,0.199 -3.202,0.242 -3.189,0.285 -3.175,0.327 -3.159,0.369 -3.141,0.409 -3.12,0.449 -3.098,0.488 -3.075,0.525 -3.049,0.562 -3.022,0.597 -2.993,0.631 -2.963,0.664 -2.931,0.695 -2.898,0.724 -2.863,0.752 -2.827,0.779 -2.79,0.803 -2.752,0.826 -2.713,0.847 -2.672,0.866 -2.631,0.884 -2.589,0.899 -2.547,0.912 -2.504,0.924 -2.46,0.933 -2.416,0.94 -2.372,0.946 -2.328,0.949
  silkscreen extent -1.95,-2.33 0.7,2.33
SW-SMD_L6.0-W3.7-LS8.0 [mm]
  rect 1.75x1 smd: 1(-3.875,0) 2(3.875,0)
  silkscreen extent -3,-1.9 3,1.9
SW-SMD_MST22D18G2 [mm]
  rect 1.2x2 smd: 1(-2.5,2.85) 2(0,2.85) 3(2.5,2.85) 4(-2.5,-2.85) 5(0,-2.85) 6(2.5,-2.85)
  silkscreen extent -4.6,-1.78 4.57,1.8
TSSOP-16_L5.0-W4.4-P0.65-LS6.4-BL [mil]
  oval 13.5x68.2 smd: 1(-89.6,-112.8) 2(-64,-112.8) 3(-38.4,-112.8) 4(-12.8,-112.8) 5(12.8,-112.8) 6(38.4,-112.8) 7(64,-112.8) 8(89.6,-112.8) 9(89.6,112.8) 10(64,112.8) 11(38.4,112.8) 12(12.8,112.8) 13(-12.8,112.8) 14(-38.4,112.8) 15(-64,112.8) 16(-89.6,112.8)
  silkscreen extent -120,-119 101,70
USB-C-SMD_TYPE-C-6PIN-2MD-073 [mm]
  rect 0.55x1.1 smd: 1(-3.2,2.375) 2(-2.4,2.375) 11(2.4,2.375) 12(3.2,2.375)
  rect 0.3x1.1 smd: 3(-1.75,2.375) 4(-1.25,2.375) 5(-0.75,2.375) 6(-0.25,2.375) 7(0.25,2.375) 8(0.75,2.375) 9(1.25,2.375) 10(1.75,2.375)
  oval 1.2x1.8 hole 0.6 slot 1.2 at 90 deg: 13(-4.325,-2.375) 14(4.325,-2.375)
  oval 1.1x2 hole 0.6 slot 1.5 at 90 deg: 13(-4.325,1.825) 14(4.325,1.825)
  Board Outline Layer circle w0.005: c-2.89,1.305 r0.35
  Board Outline Layer circle w0.005: c2.89,1.305 r0.35
  Board Outline Layer circle w0.254: c-2.89,1.305 r0.35
  Board Outline Layer circle w0.254: c2.89,1.305 r0.35
  Multi-Layer board cut-out: -3.24,1.305 -3.205,1.153 -3.108,1.031 -2.968,0.964 -2.812,0.964 -2.672,1.031 -2.574,1.153 -2.54,1.305 -2.54,1.305 -2.587,1.48 -2.715,1.608 -2.89,1.655 -3.065,1.608 -3.193,1.48 -3.24,1.305
  Multi-Layer board cut-out: 2.54,1.305 2.575,1.153 2.672,1.031 2.812,0.964 2.968,0.964 3.108,1.031 3.206,1.153 3.24,1.305 3.24,1.305 3.193,1.48 3.065,1.608 2.89,1.655 2.715,1.608 2.587,1.48 2.54,1.305
  silkscreen extent -4.5,-4.97 4.57,0.6
椭圆白头按钮开关 [mm]
  rrect10% 1.2x0.65 smd: 1(-2.38,-1.164) 2(2.39,-1.164) 3(2.39,1.216) 4(-2.38,1.216)
  silkscreen extent -2.2,-1.65 2.2,1.75

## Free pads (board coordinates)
  round 236.22 hole 157.48: 1(3332.25,3250.1) 1(3332.25,5218.6) 1(6875.56,3250.1) 1(6875.56,5218.6)

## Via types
v1: diameter 17.7, hole 12, Top Layer to Bottom Layer, 177 vias
v2: diameter 22, hole 14, Top Layer to Bottom Layer, 62 vias
v3: diameter 17.7, hole 12.01, Top Layer to Bottom Layer, 6 vias
v4: diameter 24, hole 15, Top Layer to Bottom Layer, 1 vias

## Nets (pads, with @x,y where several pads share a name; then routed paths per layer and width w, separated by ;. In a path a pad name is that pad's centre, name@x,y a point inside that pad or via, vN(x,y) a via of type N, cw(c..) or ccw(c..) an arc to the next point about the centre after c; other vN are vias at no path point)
$1N4607: LED3.1 R6.1 | length 144.4
  Top Layer w8: R6.1@5713.3,4988.26 5742.96,4958.6 LED3.1@5845.45,4958.6
$1N5052: C13.2 U1.73 | length 98
  Top Layer w8: C13.2@4198.3,4613.6 4198.39,4613.51 U1.73@4198.39,4515.64
$1N8262: R10.2 U4.3 | length 108.1
  Top Layer w8: v1(3677.9,4846.6) R10.2@3677.9,4898.33
  Bottom Layer w8: v1(3677.9,4846.6) 3712.61,4881.31 U4.3@3712.61,4888.6
$1N11541: C23.2 U1.49 | length 100.3
  Top Layer w8: U1.49@4692.48,4450.89 4792.52,4450.89 C23.2@4792.68,4451.05
$1N13723: C26.1 U5.8 | length 118.1
  Bottom Layer w8: C26.1@4067.43,4905.34 U5.8@4185.14,4905.34
  Bottom Layer w12: U5.8@4185.14,4905.34 U5.8@4185.41,4905.62
$1N14257: R2.1 R3.2 U2.1 | length 268.4
  Bottom Layer w12: R2.1@5713.88,4528.26 5776.24,4528.26 5847.44,4457.06 U2.1@5867.09,4457.06 5897.36,4457.06 5909.24,4468.94 R3.2@5947.9,4468.94
$1N21384: Q3.1 R27.2 R30.1 | length 162.2
  Top Layer w8: Q3.1@5664.5,3711.73 5664.5,3625.55 R27.2@5664.22,3625.27 R30.1@5739.86,3625.27
$1N21387: R26.1 U7.12 | length 686.6
  Top Layer w12: R26.1@5552.4,3734.86 v2(5587.38,3734.86)
  Bottom Layer w12: v2(5587.38,3734.86) 5949.07,4096.55 U7.12@6089.18,4096.55
$1N21388: Q3.3 U7.11 | length 585.9
  Top Layer w12: Q3.3@5701.9,3790.47 5701.9,3823.36 5825.9,3947.36 v2(5825.9,4017.6)
  Bottom Layer w12: v2(5825.9,4017.6) 5932.41,4124.11 U7.11@6089.18,4124.11
$1N24716: R25.2 U10.2 | length 178.2
  Top Layer w8: U10.2@5127.52,4307.53 5191.37,4307.53 5238.87,4260.03 R25.2@5238.87,4212.84
$1N25477: CN1.3 R22.1 R24.1 U6.6 | length 356.6
  Top Layer w8: CN1.3@6348.51,3389.78 v1(6348.51,3442.72)
  Bottom Layer w8: v1(6348.51,3442.72) 6348.51,3471.94 6353.56,3476.99 R22.1@6353.56,3482.79 ; U6.6@6348.9,3621.1 6348.9,3574.71 6330.9,3556.71 6330.9,3530.46 6353.56,3507.8 R22.1@6353.56,3482.79 ; R24.1@6459.86,3482.79 R22.1@6353.56,3482.79
$1N25478: CN1.2 R20.1 R22.2 U6.7 | length 356.6
  Top Layer w8: CN1.2@6299.29,3389.78 v1(6299.29,3442.72)
  Bottom Layer w8: R20.1@6187.94,3482.79 R22.2@6294.24,3482.79 ; U6.7@6298.9,3621.1 6298.9,3574.71 6316.9,3556.71 6316.9,3530.46 6294.24,3507.8 R22.2@6294.24,3482.79 ; v1(6299.29,3442.72) 6299.29,3471.94 6294.24,3476.99 R22.2@6294.24,3482.79
$1N28487: R15.2 USB1.4 | length 91.8
  Top Layer w8: USB1.4@4877.51,4987.29 4877.7,4987.1 4877.7,4923.14 R15.2@4897.2,4903.64
$1N28620: R21.2 USB1.10 | length 83
  Top Layer w8: R21.2@4759.4,4904.33 USB1.10@4759.4,4987.29
$1N28747: R16.2 USB2.4 | length 91.8
  Top Layer w8: USB2.4@5428.7,4987.3 5428.7,4923.34 R16.2@5448.4,4903.64
$1N28749: R23.2 USB2.10 | length 83.6
  Top Layer w8: R23.2@5310.59,4903.67 USB2.10@5310.59,4987.3
$1N31567: F1.2 | length 124.5
  Bottom Layer w12: F1.2@5677.38,4910.6 5801.89,4910.6
$1N34636: LED2.1 R9.1 | length 127.7
  Top Layer w8: LED2.1@3710.89,4321.66 R9.1@3838.63,4321.66
$1N34643: LED1.1 R5.1 | length 127.1
  Top Layer w8: LED1.1@3711.38,4426.73 3814.24,4426.73 ; 3814.38,4426.6 3814.24,4426.73 ; R5.1@3838.24,4426.73 3814.24,4426.73
$1N34651: LED5.1 R13.1 | length 144.9
  Top Layer w8: LED5.1@4361.85,4958.6 4464.84,4958.6 R13.1@4494.5,4988.26
$1N41751: LED4.2 R7.1 | length 119.7
  Top Layer w8: LED4.2@3714.79,4176.74 3834.38,4176.74 R7.1@3834.46,4176.81
$1N56661: C1.2 U1.6 | length 123.8
  Top Layer w12: C1.2@4257.4,3813.26 U1.6@4257.44,3937.11
$1N85266: C3.1 C4.2 D1.1 Q1.3 | length 612.9
  Top Layer w12: C4.2@4024.5,4813.06 4044.18,4832.74 C3.1@4139.5,4832.74 ; D1.1@4139.5,4912.44 C3.1@4139.5,4832.74 ; 4236.1,4650.7 4186,4700.8 4186,4786.24 C3.1@4139.5,4832.74 ; 4237.44,4650.7 4355.24,4650.7 4375.55,4671.01 Q1.3@4375.55,4712.45
$1N85309: C7.1 C8.2 D2.1 Q2.3 | length 373
  Top Layer w8: 6110.75,4832.77 6111.5,4833.52
  Top Layer w12: Q2.3@5950.36,4712.45 6068.31,4830.4 C7.1@6068.31,4832.77 6110.75,4832.77 6163.63,4832.77 C8.2@6183.31,4813.09 ; C7.1@6068.31,4832.77 D2.1@6068.3,4912.44
$1N95889: FPC1.29 FPC1.30 | length 965.4
  Bottom Layer w12: FPC1.30@4818.47,4790.13 4828.57,4790.13 FPC1.29@4838.15,4790.13
  Bottom Layer w20: 4828.57,4790.13 4828.57,4820.82 4869.64,4861.88 5425.88,4861.88 5632.56,4655.2 5640.99,4655.2
$1N102744: LED6.1 U12.15 | length 4855
  Inner1 w15: v1(5654.78,5107.6) 6343.9,5107.6 6432.5,5196.2 6595.3,5196.2 6863.9,4927.6 6863.9,3723.6 6752.9,3612.6 v1(6013.9,3612.6)
  Inner2 w15: v1(5430.9,4031.58) 5476.92,4031.58 5767.9,3740.6 5885.9,3740.6 v1(6013.9,3612.6)
  Bottom Layer w12: LED6.1@5103.9,5191.41 5114.28,5191.41 5198.1,5107.6 v1(5654.78,5107.6) ; U12.15@5375.1,4031.6 v1(5430.9,4031.58)
$1N102783: LED6.2 R32.1 | length 79.5
  Bottom Layer w12: R32.1@5103.9,5026.26 LED6.2@5103.9,5105.78
$1N102997: LED7.2 R33.1 | length 105.3
  Bottom Layer w12: LED7.2@6353.9,5105.78 R33.1@6459.24,5105.8
$1N103001: LED7.1 U12.14 | length 3401.4
  Inner1 w15: v1(5898.9,3644.75) 6735.45,3644.75 6825.9,3735.2 6825.9,4877.31 v1(6545.4,5157.81)
  Inner2 w15: v1(5452.9,4005.6) 5747.05,3711.45 5865.05,3711.45 5898.9,3677.6 v1(5898.9,3644.75)
  Bottom Layer w12: U12.14@5375.1,4006 5452.51,4005.99 v1(5452.9,4005.6) ; LED7.1@6353.9,5191.41 6387.5,5157.81 v1(6545.4,5157.81)
$1N103337: LED8.2 R34.1 | length 78.2
  Bottom Layer w12: R34.1@6675.83,4155.61 LED8.2@6754,4155.61
$1N103341: LED8.1 U12.13 | length 1812
  Inner2 w15: v1(5430.9,3980.39) 5730.69,3680.6 v1(5851.9,3680.6)
  Bottom Layer w12: U12.13@5375.1,3980.4 v1(5430.9,3980.39) ; v1(5851.9,3680.6) 5933.9,3680.6 6174.9,3921.6 6612.9,3921.6 6754.77,4063.47 6792.77,4063.47 6839.63,4110.33 LED8.1@6839.63,4155.61
$1N103422: LED9.2 R35.1 | length 124.3
  Bottom Layer w12: R35.1@6229.56,3361.4 LED9.2@6353.9,3361.41
$1N103426: LED9.1 U12.12 | length 1335.6
  Bottom Layer w12: U12.12@5375.1,3954.8 5433.7,3954.8 5489.9,3898.6 5489.9,3769.61 5983.72,3275.78 LED9.1@6353.9,3275.78
$1N103507: LED10.2 R36.1 | length 127.3
  Bottom Layer w12: LED10.2@5103.9,3361.41 R36.1@5231.24,3361.4
$1N103511: LED10.1 U12.11 | length 953
  Bottom Layer w12: LED10.1@5103.9,3275.78 5035.72,3275.78 5022.9,3288.6 5022.9,3386.6 5444.9,3808.6 5444.9,3897.6 5413.29,3929.21 U12.11@5375.1,3929.2
$1N103592: LED11.2 R38.1 | length 84.4
  Bottom Layer w12: LED11.2@3453.8,4155.61 R38.1@3538.18,4155.61
$1N103596: LED11.1 U12.10 | length 2409.3
  Bottom Layer w12: LED11.1@3368.17,4155.61 3368.17,4132.6 3407.92,4092.85 3699.13,4092.85 4231.79,3560.2 4989.5,3560.2 5332.92,3903.62 U12.10@5375.1,3903.6
$1N103677: LED13.2 R39.1 | length 120.3
  Bottom Layer w12: R39.1@3733.56,3361.4 LED13.2@3853.9,3361.41
$1N103681: LED13.1 U12.9 | length 1770.6
  Bottom Layer w12: LED13.1@3853.9,3275.78 3970.09,3275.78 4230.4,3536.1 5033.15,3536.1 U12.9@5375.1,3878
$1N103762: LED12.2 R37.1 | length 141.2
  Bottom Layer w12: LED12.2@3853.9,5105.78 3953.32,5105.78 R37.1@3982.83,5076.28
$1N103766: LED12.1 U12.7 | length 3883.2
  Top Layer w12: v1@5265.37,3903.62 v1(5651.17,3903.62)
  Bottom Layer w12: LED12.1@3853.9,5191.41 3740.81,5191.41 3403.9,4854.5 3403.9,4330.6 3439.9,4294.6 3585.9,4294.6 3663.9,4216.6 3663.9,4164.6 4244.5,3584 4945.75,3584 v1(5265.33,3903.58) ; U12.7@5600.7,3903.6 v1(5651.17,3903.62)
$1N129348: R11.2 U4.4 | length 224.8
  Top Layer w8: v1(3771.4,4846.92) R11.2@3771.4,4898.65
  Bottom Layer w8: v1(3771.4,4846.92) 3813.08,4888.6 U4.4@3927.18,4888.6
+3.3V_1: C1.1 C5.1 C6.2 C15.2 C16.2 C17.2 C18.2 C19.2 C20.2 C21.2 CN2.4 CN3.4 FPC2.1 FPC3.1 FPC4.6 FPC5.6 H1.7 H1.8 LED1.2 LED2.2 Q1.2 R4.1 R7.2 R13.2 R14.2 R28.1 R29.1 U1.11 U1.19 U1.22 U1.28 U1.50 U1.75 U1.100 U4.1 U4.2 U8.6 U9.6 | length 10061.5
  Top Layer w8: LED2.2@3647.43,4321.9 LED2.2@3647.91,4321.42 ; R14.2@3694.38,4036.44 3694.38,4098.53 ; U1.11@4355.87,3937.11 4355.87,3974.94 4399.47,4018.54 v1(4513.35,4018.54) U1.19@4513.35,3937.11 ; C5.1@4494.5,4832.74 R13.2@4494.5,4928.94 ; R28.1@4633.9,3513.14 4633.9,3528.26 4777.59,3671.95 ; v1@4735.22,4470.57 v1(4735.42,4470.77) ; 5539.58,3588.82 5539.58,3547.46 R29.1@5573.9,3513.14
  Top Layer w12: v2(3472.8,4524.51) 3674.9,4524.51 ; FPC4.6@3483.1,3917 3483.11,4015.25 3566.39,4098.53 ; FPC2.1@3494.4,4677.7 3674.9,4677.7 ; LED2.2@3647.43,4321.9 LED1.2@3647.43,4426.46 3674.9,4453.93 3674.9,4524.51 ; LED2.2@3647.91,4321.42 3566.39,4239.83 3566.39,4098.53 ; v2(3820.14,4788.6) 3820.14,4677.7 ; R7.2@3872.75,4176.81 3872.75,4098.53 ; C17.2@4067.46,3929.04 3897.98,4098.53 3872.75,4098.53 ; U1.100@4098,3998.13 4098,3958.24 C17.2@4068.8,3929.04 4239.7,3758.14 C1.1@4257.4,3758.14 4280.44,3758.14 4335.56,3813.26 C21.2@4355.9,3813.26 U1.11@4355.87,3937.11 ; U1.75@4158.98,4531.54 C15.2@4099.3,4531.54 v2(4099.3,4590.74) 4012.34,4677.7 3820.14,4677.7 ; v2(4266.04,4817.24) 4314.49,4817.24 Q1.2@4316.49,4819.24 4329.99,4832.74 C5.1@4494.5,4832.74 4589.82,4832.74 C6.2@4609.5,4813.06 ; U1.19@4513.35,3937.11 4513.35,3904.55 4531.92,3885.98 4572.41,3885.98 ; U1.22@4572.41,3937.11 4572.41,3885.98 ; U1.28@4692.48,4037.5 4764.04,4037.5 ; U1.50@4692.48,4470.57 v1@4735.22,4470.57 ; U1.50@4692.68,4470.77 C16.2@4692.68,4542.54 ; R4.1@4695.49,3754.04 4777.59,3671.95 5456.45,3671.95 5539.58,3588.82 6101.12,3588.82 6135.9,3623.6 6517.65,3623.6 v2(6589.65,3695.6) 6614.23,3720.18 FPC5.6@6724.7,3720.2 6773.48,3720.18 6792.9,3739.6 6792.9,3931.6 6735,3989.5 v2(6735,4273.45) 6713.4,4295.05 FPC3.1@6713.4,4559.5 6691.2,4559.5 v2(6544.1,4706.6) ; R4.1@4697.59,3756.15 C19.2@4697.59,3841.55 4697.59,3885.98 ; C20.2@4697.59,3929.05 4697.59,3885.98 ; C20.2@4698.93,3929.05 4764.04,3994.16 4764.04,4037.5 ; C18.2@4805.23,4037.5 4764.04,4037.5 ; 3566.39,4098.53 3694.38,4098.53 3872.75,4098.53 ; 3674.9,4524.51 3674.9,4677.7 ; 3674.9,4677.7 3820.14,4677.7 ; 4572.41,3885.98 4697.59,3885.98
  Bottom Layer w8: v1(4513.35,4018.54) 4575.2,4080.4 4653.1,4080.4 4703.64,4130.95 4703.64,4438.99 v1(4735.42,4470.77)
  Bottom Layer w12: CN2.4@3472.8,4492.42 v2(3472.8,4524.51) ; U8.6@3482.8,3941.63 3483.51,3942.34 v2(3483.51,3981.56) ; U4.1@3712.61,4788.6 v2(3820.14,4788.6) U4.2@3927.18,4788.6 ; v2(4099.3,4590.74) 4178.34,4590.74 4266.04,4678.44 v2(4266.04,4817.24) ; H1.7@6284.37,4706.8 H1.8@6467.83,4706.8 ; H1.8@6482.1,4706.6 v2(6544.1,4706.6) ; v2(6589.65,3695.6) U9.6@6725,3695.57 ; v2(6735,4273.45) CN3.4@6735,4344.78
+3.3V_2: C9.1 C10.2 C30.2 C31.2 Q2.2 R6.2 R26.2 SW2.1 U7.10 U10.1 | length 3331.1
  Top Layer w8: C9.1@5713.31,4832.77 R6.2@5713.3,4928.94
  Top Layer w12: U10.1@5080.28,4307.53 5080.28,4346.18 5095.03,4360.93 v2(5158.42,4360.93) ; SW2.1@5216.1,4713.52 5154.23,4651.65 5154.23,4486.27 v2(5393.21,4247.29) ; R26.2@5552.4,3768.64 v2(5587.38,3768.64)
  Top Layer w15: SW2.1@5216.1,4713.52 5283.82,4713.52 5294.86,4724.56 C30.2@5362.4,4724.56 5419.56,4724.56 ; v2(5419.56,4572.24) 5419.56,4724.56 ; v2(5473.9,4753.6) C31.2@5473.9,4724.56 5419.56,4724.56 ; v2(5568.9,4813.09) C10.2@5598.31,4813.09 5617.99,4832.77 C9.1@5713.31,4832.77 5877.77,4832.77 Q2.2@5891.3,4819.24
  Inner1 w20: v2(5473.9,4753.6) 5533.39,4813.09 v2(5568.9,4813.09)
  Inner2 w12: v2(5158.42,4360.93) 5331.23,4360.93 5419.56,4449.26 v2(5419.56,4572.24)
  Bottom Layer w12: v2(5393.21,4247.29) 5488.83,4151.67 5742.15,4151.67 ; v2(5587.38,3768.64) 5742.15,3923.41 5742.15,4151.67 ; U7.10@6072.4,4151.67 5742.15,4151.67
+5V: C24.2 C25.2 C27.2 C29.2 CN1.1 D1.2 D2.2 D3.5 R1.1 R17.1 R24.2 U5.5 U6.8 U11.3 U12.6 U12.16 | length 7911.1
  Top Layer w12: D1.2@4139.5,5004.77 4231.36,4912.9 4429.25,4912.9 v2(4461.55,4880.6) ; v4@5961.45,4655.55 6114.9,4502.1 v2(6114.9,3710.6) ; v2(6042,5004.8) D2.2@6068.3,5004.77 ; CN1.1@6250.08,3389.78 v2@6250.08,3442.42
  Top Layer w15: v4(5960.95,4656.05) v4@5961.45,4655.55
  Inner1 w12: v2(3768.9,3730.7) 3768.9,3887.6 3687.9,3968.6 3687.9,4070 3903.01,4285.11 3903.01,4563.71 3977,4637.7 v2(4099.3,4637.7)
  Inner1 w20: v2(4461.55,4880.6) 5580.9,4880.6 5598.4,4898.1 5718.9,4898.1 v4(5960.95,4656.05)
  Inner2 w12: v1(5392.9,4165.6) 5470.9,4243.6 v1(5470.9,4500.9)
  Bottom Layer w12: v2(3768.9,3730.7) U11.3@3768.9,3805.1 ; v2(4099.3,4637.7) 4137.1,4637.7 C29.2@4185.4,4686 U5.5@4185.41,4755.62 4206.92,4755.62 4240.9,4789.6 4240.9,4824.6 4296.9,4880.6 v2(4461.55,4880.6) D3.5@4499.66,4880.6 ; v1(5392.9,4165.6) 5375.07,4147.77 U12.16@5375.1,4057.2 5434.8,4057.17 5562.76,3929.21 U12.6@5600.7,3929.2 ; v1(5470.9,4500.9) 5470.9,4545.6 5514,4588.7 5632.37,4588.7 ; R1.1@5632.4,4528.26 5632.37,4588.7 ; 5814.21,4655.2 5747.71,4588.7 5632.37,4588.7 ; v4(5960.95,4656.05) 6098.1,4793.2 C25.2@6098.1,4910.6 6042,4910.6 ; 5975.11,4910.6 6042,4910.6 ; v2(6042,5004.8) 6042,4910.6 ; C24.2@6065.9,3621.1 6114.9,3621.1 ; R17.1@6163.9,3710.56 v2(6114.9,3710.6) 6114.9,3621.1 ; v2(6250.08,3442.88) 6246.77,3439.57 6140.93,3439.57 6114.9,3465.6 6114.9,3621.1 ; R24.2@6493.94,3482.79 6493.94,3631.56 6440.9,3684.6 6266.9,3684.6 6248.9,3666.6 U6.8@6248.9,3621.1 C27.2@6163.9,3621.1 6114.9,3621.1
  Bottom Layer w20: 5814.21,4655.2 v4@5960.1,4655.2
BACKLIGHT: R27.1 U1.92 | length 1751.8
  Top Layer w8: U1.92@4098,4155.61 v1(4140.94,4155.61) ; v1(4746.9,3792.54) 5151.06,3792.54 5248.4,3695.2 5473,3695.2 5542.93,3625.27 5596,3625.27 ; 5596,3625.2 5596.07,3625.27 R27.1@5630.14,3625.27
  Inner1 w8: v1(4140.94,4155.61) 4371.95,3924.6 4454.1,3924.6 4487.7,3891 4606.8,3891 4705.26,3792.54 v1(4746.9,3792.54)
BACKLIGHT_ADC: C34.1 R25.1 U1.23 | length 988.2
  Top Layer w8: U1.23@4592.09,3937.11 v1(4592.09,3980.05) ; v1(4848.5,3892.1) 4915.1,3958.7 5130.4,3958.7 5228.26,4056.56 C34.1@5238.87,4056.56 v1(5276.54,4056.6) ; R25.1@5238.87,4178.76 v1(5270.5,4178.8)
  Bottom Layer w8: v1(4592.09,3980.05) 4680.04,3892.1 v1(4848.5,3892.1) ; v1(5270.5,4178.8) 5270.5,4122.6 5276.54,4116.56 v1(5276.54,4056.6)
BOOT0: R10.1 U1.94 | length 1183.2
  Top Layer w8: v1(3616.66,4932.36) 3677.81,4932.36 R10.1@3677.88,4932.43 ; v1(4055.06,4116.24) U1.94@4098,4116.24
  Inner2 w8: v1(3616.66,4932.36) 3616.66,4550.08 3756.9,4409.84 3756.9,4275.6 3916.26,4116.24 v1(4055.06,4116.24)
BOOT1: R11.1 U1.37 | length 1355.6
  Top Layer w8: R11.1@3771.4,4932.43 v1(3832.54,4932.43) ; v1(4649.53,4214.67) U1.37@4692.48,4214.67
  Inner1 w8: v1(3832.54,4932.43) 3961.57,4932.43 4140.7,4753.3 4140.7,4519.04 4190.98,4468.76 4215.59,4468.76 4469.68,4214.67 v1(4649.53,4214.67)
CAN1_RX: U1.81 U11.4 | length 784.1
  Top Layer w8: v1(4055.05,4372.15) U1.81@4098,4372.15
  Inner1 w8: v1(3759.9,4000.6) 3759.9,4019.45 3750.9,4028.45 3750.9,4056 3981.5,4286.6 4017.91,4286.6 4055.05,4323.75 v1(4055.05,4372.15)
  Bottom Layer w8: v1(3759.9,4000.6) 3759.9,3977.6 3750.9,3968.6 3750.9,3896.27 3818.9,3828.27 U11.4@3818.9,3821.1 ; U11.4@3818.9,3805.1 U11.4@3818.9,3812.27
CAN1_TX: U1.82 U11.1 | length 784
  Top Layer w8: v1(4035.45,4352.46) U1.82@4098,4352.46
  Inner1 w8: v1(3727.9,4000.6) 3727.9,4019.45 3736.9,4028.45 3736.9,4065.8 3971.7,4300.6 4012.11,4300.6 4035.45,4323.95 v1(4035.45,4352.46)
  Bottom Layer w8: U11.1@3668.9,3805.1 U11.1@3668.9,3812.27 ; U11.1@3668.9,3821.1 3668.9,3828.27 3736.9,3896.27 3736.9,3968.6 3727.9,3977.6 v1(3727.9,4000.6)
CAN_H: CN4.1 R31.2 U11.7 | length 415.5
  Top Layer w8: CN4.1@3859.3,3389.19 v1(3859.3,3442.13)
  Bottom Layer w8: U11.7@3718.9,3608.1 3718.9,3519.06 3714.24,3514.4 R31.2@3714.24,3508.6 3736.9,3485.94 3736.9,3459.6 3763.22,3433.28 3803.58,3433.28 3843.7,3473.4 3871.24,3473.4 3876.9,3467.74 3876.9,3459.74 v1(3859.3,3442.13)
CAN_L: CN4.2 R31.1 U11.6 | length 415.5
  Top Layer w8: CN4.2@3908.51,3389.19 v1(3908.51,3442.13)
  Bottom Layer w8: U11.6@3768.9,3608.1 3768.9,3519.06 3773.56,3514.4 R31.1@3773.56,3508.6 3750.9,3485.94 3750.9,3465.4 3769.02,3447.28 3797.78,3447.28 3837.9,3487.4 3877.04,3487.4 3890.9,3473.54 3890.9,3459.74 v1(3908.51,3442.13)
CH340_RX: R5.2 R8.1 U5.7 | length 650.8
  Top Layer w8: R5.2@3872.75,4426.6 3947.86,4426.6 3947.86,4520.4 v1(3923.86,4544.4)
  Bottom Layer w8: v1(3923.86,4544.4) 3923.86,4588.56 4112.9,4777.6 4112.9,4831.6 4136.92,4855.62 U5.7@4185.41,4855.62
CH340_TX: R9.2 R12.1 U5.6 | length 681.1
  Top Layer w8: R9.2@3872.75,4321.71 3947.86,4321.71 3947.86,4379.66 v1(3948,4379.8)
  Bottom Layer w8: v1(3948,4379.8) 3968.78,4400.58 ; 3968.78,4607.48 4127.9,4766.6 4127.9,4788.6 4144.92,4805.62 U5.6@4185.41,4805.62 ; 3970.12,4400.58 3970.12,4607.48
D+: D3.1 USB1.6 USB1.8 | length 392.6
  Top Layer w8: v1(4798.78,4950.63) USB1.8@4798.78,4987.29 4798.78,5017.82 4808.61,5027.65 4828.3,5027.65 4838.15,5017.79 USB1.6@4838.15,4987.29
  Bottom Layer w8: D3.1@4590.14,4918 4607.07,4901.07 4615.38,4901.07 4628.86,4887.6 4647.1,4887.6 4704.47,4944.97 4793.13,4944.97 v1(4798.78,4950.63)
D-: D3.3 USB1.5 USB1.7 | length 392.2
  Top Layer w8: USB1.7@4818.46,4987.29 4818.46,4961.75 4829.58,4950.63 v1(4838.15,4950.63) 4846.75,4950.63 4857.83,4961.71 USB1.5@4857.83,4987.29
  Bottom Layer w8: D3.3@4590.14,4843.2 4607.07,4860.13 4639.43,4860.13 4710.27,4930.97 4818.5,4930.97 v1(4838.15,4950.63)
DGND: C2.2 C3.2 C4.1 C5.2 C6.1 C7.2 C8.1 C9.2 C10.1 C11.1 C12.2 C13.1 C15.1 C16.1 C17.1 C18.1 C19.1 C20.1 C21.1 C23.1 C24.1 C25.1 C26.2 C27.1 C28.1 C29.1 C30.1 C31.1 C32.1 C33.1 C34.2 CN1.4 CN2.1 CN3.1 D3.2 FPC1.1 FPC2.4 FPC3.4 FPC4.1 FPC5.1 H1.1 H1.2 LED3.2 LED5.2 Q1.1 Q2.1 Q3.2 R3.1 R15.1 R16.1 R20.2 R21.1 R23.1 R30.2 SW1.1 SW2.4 SW2.5 SW3.3 SW3.4 SW4.3 SW4.4 U1.10 U1.20 U1.27 U1.74 U1.99 U2.3 U4.5 U4.6 U5.3 U6.5 U7.8 U7.13 U8.1 U9.1 U10.4 U10.5 U10.6 U11.2 U11.8 U12.4 U12.5 U12.8 USB1.1 USB1.12 USB1.13 USB1.14 USB2.1 USB2.12 USB2.13 USB2.14 X1.2 X1.4 | length 907.5
  Top Layer w8: v3(4427.84,3736.77) 4427.84,3802.79 C12.2@4447.84,3822.79 ; U1.20@4533.04,3937.11 4533.04,3999.04 v2(4561.54,4027.54) ; C2.2@4600.76,3822.79 4620.76,3802.79 v3(4620.76,3736.87) ; U1.27@4692.48,4017.81 4733.52,4017.81 v1(4743.19,4008.14)
  Top Layer w10: X1.4@4481.49,3737 4481.25,3736.77 v3(4427.84,3736.77) v3(4427.84,3669.69) 4427.84,3642 4452.3,3617.54 v3(4481.49,3617.54) v3(4567.6,3617.54) ; v3(4620.76,3736.87) v3(4620.76,3669.78) ; v3(4567.6,3617.54) 4596.3,3617.54 4620.76,3642 v3(4620.76,3669.78) ; v3(4567.6,3617.54) 4567.6,3669.56 X1.2@4568.11,3670.07 4568.4,3669.78 v3(4620.76,3669.78)
  other v1: 4852.9,4101.94 4995.99,4192.15 4881.87,4194.14 4773.93,4196.14 4856.99,4208.09 4906.74,4208.09
  other v2: 6163.9,3522.23 6394.78,3553.97 6429.78,3553.97 6464.78,3553.97 6212.77,3566 4871.2,3717.7 4851.2,3747.7 4890.76,3747.7 5103.9,3865.19 5138.35,3865.19 5201.35,3909.87 5201.35,3939.32 4593.37,4027.54 4625.21,4027.54 5531,4039.9 4376.78,4046.71 4326.78,4081.71 4376.78,4081.71 4426.78,4081.71 4376.78,4116.71 3556.9,4324.6 3528.87,4344.78 4724.42,4498.93 6762.9,4529.6 4024.24,4572.6 5453.9,4593.6 4644.24,4597.7 4004.24,4602.6 4043.8,4602.6 6056.49,4618 6092.7,4618 5382.46,4627.6 4692.7,4645.05 5415.7,4794.3 5415.7,4824.3 5491.2,4846.6 5462.5,4931.98
LEDA: U1.60 U12.1 | length 3174.3
  Top Layer w8: v1(4292.24,4440.54) 4409.84,4440.54 4454.3,4485 U1.60@4454.3,4531.59
  Inner1 w8: v1(4003.24,4183.6) 4003.24,3996.94 3942.9,3936.6 3942.9,3791.6 4245.9,3488.6 5080.9,3488.6 v1(5648.9,4056.6)
  Inner2 w8: v1(4003.24,4183.6) 4094.18,4274.54 4159.68,4274.54 4230.24,4345.11 4230.24,4378.54 v1(4292.24,4440.54)
  Bottom Layer w8: U12.1@5600.7,4057.2 5648.33,4057.17 v1(5648.9,4056.6)
LEDB: U1.61 U12.2 | length 3274.1
  Top Layer w8: v1(4317.24,4460.39) 4400.29,4460.39 4434.61,4494.71 U1.61@4434.61,4531.59
  Inner1 w8: v1(3977.24,4183.6) 3977.24,3996.94 3920.67,3940.37 3920.67,3777.83 4229.9,3468.6 5103.92,3468.6 v1(5666.9,4031.58)
  Inner2 w8: v1(3977.24,4183.6) 3977.24,4229.6 4060.18,4312.54 4167.24,4312.54 4209.3,4354.61 4209.3,4390.66 4279.03,4460.39 v1(4317.24,4460.39)
  Bottom Layer w8: U12.2@5600.7,4031.6 v1(5666.9,4031.58)
LEDC: U1.62 U12.3 | length 3389.6
  Top Layer w8: v1(4340.24,4480.54) 4395.24,4480.54 4414.93,4500.23 U1.62@4414.93,4531.59
  Inner1 w8: v1(3948.9,4183.6) 3948.9,3998 3899.67,3948.77 3899.67,3764.83 4217.9,3446.6 5126.9,3446.6 v1(5685.9,4005.6)
  Inner2 w8: v1(3948.9,4183.6) 3948.9,4233.6 4045.84,4330.54 4158.79,4330.54 4189.58,4361.33 4189.58,4421.76 4275.31,4507.49 4313.29,4507.49 v1(4340.24,4480.54)
  Bottom Layer w8: U12.3@5600.7,4006 5685.51,4005.99 v1(5685.9,4005.6)
M0_ADC: FPC1.11 U1.29 | length 1248.1
  Top Layer w8: U1.29@4692.48,4057.18 4749.18,4057.18 4757.1,4065.1 4977,4065.1 v1(5033.9,4008.2)
  Bottom Layer w8: v1(5033.9,4008.2) 5172.81,4147.1 5172.81,4276.49 5133.9,4315.4 5133.9,4429.6 5192.48,4488.18 FPC1.11@5192.48,4790.13
M0_ADC_A: FPC1.18 U1.25 | length 1216.9
  Top Layer w8: U1.25@4631.46,3937.11 v1(4631.46,3980.05)
  Bottom Layer w8: v1(4631.46,3980.05) 4664.13,3980.05 4713.58,3930.6 4834.4,3930.6 5054.69,4150.89 FPC1.18@5054.69,4789.85
M0_ADC_C: FPC1.17 U1.26 | length 1115.5
  Top Layer w8: v1(4692.48,3980.8) U1.26@4692.48,3998.13
  Inner1 w8: v1(4692.48,3980.8) v1(4915.89,3980.8)
  Bottom Layer w8: v1@4915.89,3980.68 5074.38,4139.18 FPC1.17@5074.38,4789.85
M0_BK_BUTTON: C32.2 R28.2 SW3.1 SW3.2 U1.46 | length 1517.1
  Top Layer w8: R28.2@4633.9,3479.06 4783.06,3479.06 v1(4817,3513) 4921.87,3513 SW3.2@4972.56,3462.31 SW3.1@4972.55,3274.5 ; U1.46@4692.48,4391.83 v1(4735.42,4391.83)
  Inner1 w8: v1(4816.9,3950.8) 4816.9,3513.1 v1(4817,3513)
  Bottom Layer w8: v1(4735.42,4391.83) 4735.42,4193.08 4816.9,4111.6 v1(4816.9,3950.8)
M0_BK_OUT: FPC1.26 U1.2 | length 1281.3
  Top Layer w8: U1.2@4178.7,3937.11 v1(4178.7,3997.05)
  Inner1 w8: v1(4818.36,4746.5) 4837.21,4727.65 4878.35,4727.65 v1(4897.2,4746.51)
  Bottom Layer w8: v1(4178.7,3997.05) 4178.7,4115.61 4592.77,4529.68 4592.77,4635.47 4703.8,4746.5 v1(4818.36,4746.5) ; v1(4897.2,4746.51) FPC1.26@4897.2,4791.86
M0_I2C1_SCL: CN2.3 FPC2.2 U1.95 | length 1064.7
  Top Layer w8: v1(3451.46,4638.3) FPC2.2@3494.4,4638.3 ; v1(4031.75,4096.55) U1.95@4098,4096.55
  Bottom Layer w8: v1(3451.46,4638.3) 3540.48,4549.28 3540.48,4443.21 ; CN2.3@3472.8,4443.21 3540.48,4443.21 ; v1(4031.75,4096.55) 3971.7,4156.6 3791.26,4156.6 3540.48,4407.38 3540.48,4443.21
M0_I2C1_SDA: CN2.2 FPC2.3 U1.96 | length 1059.5
  Top Layer w8: v1(3451.46,4599) FPC2.3@3494.4,4599 ; v1(4055.04,4076.9) U1.96@4098,4076.87
  Bottom Layer w8: v1(3451.46,4599) 3422.64,4570.19 3422.64,4406.08 3434.74,4393.99 CN2.2@3472.8,4393.99 3528.44,4393.99 3782.72,4139.7 3960.75,4139.7 4022.76,4077.7 4054.24,4077.7 v1(4055.04,4076.9)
